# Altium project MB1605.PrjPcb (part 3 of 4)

## Sheet USB_HUB.SchDoc: USB_HUB
size A3; Date: Not used; ApprovedBy: Not used; CheckedBy: Not used; Author: Not used; CompanyName: STMicroelectronics; DrawnBy: Not used; Engineer: Not used; Organization: Not used; Address1: Not used; Address2: Not used; Address3: Not used; Address4: Not used; DocumentNumber: Not used; Revision: Not used; SheetNumber: 14; SheetTotal: 18
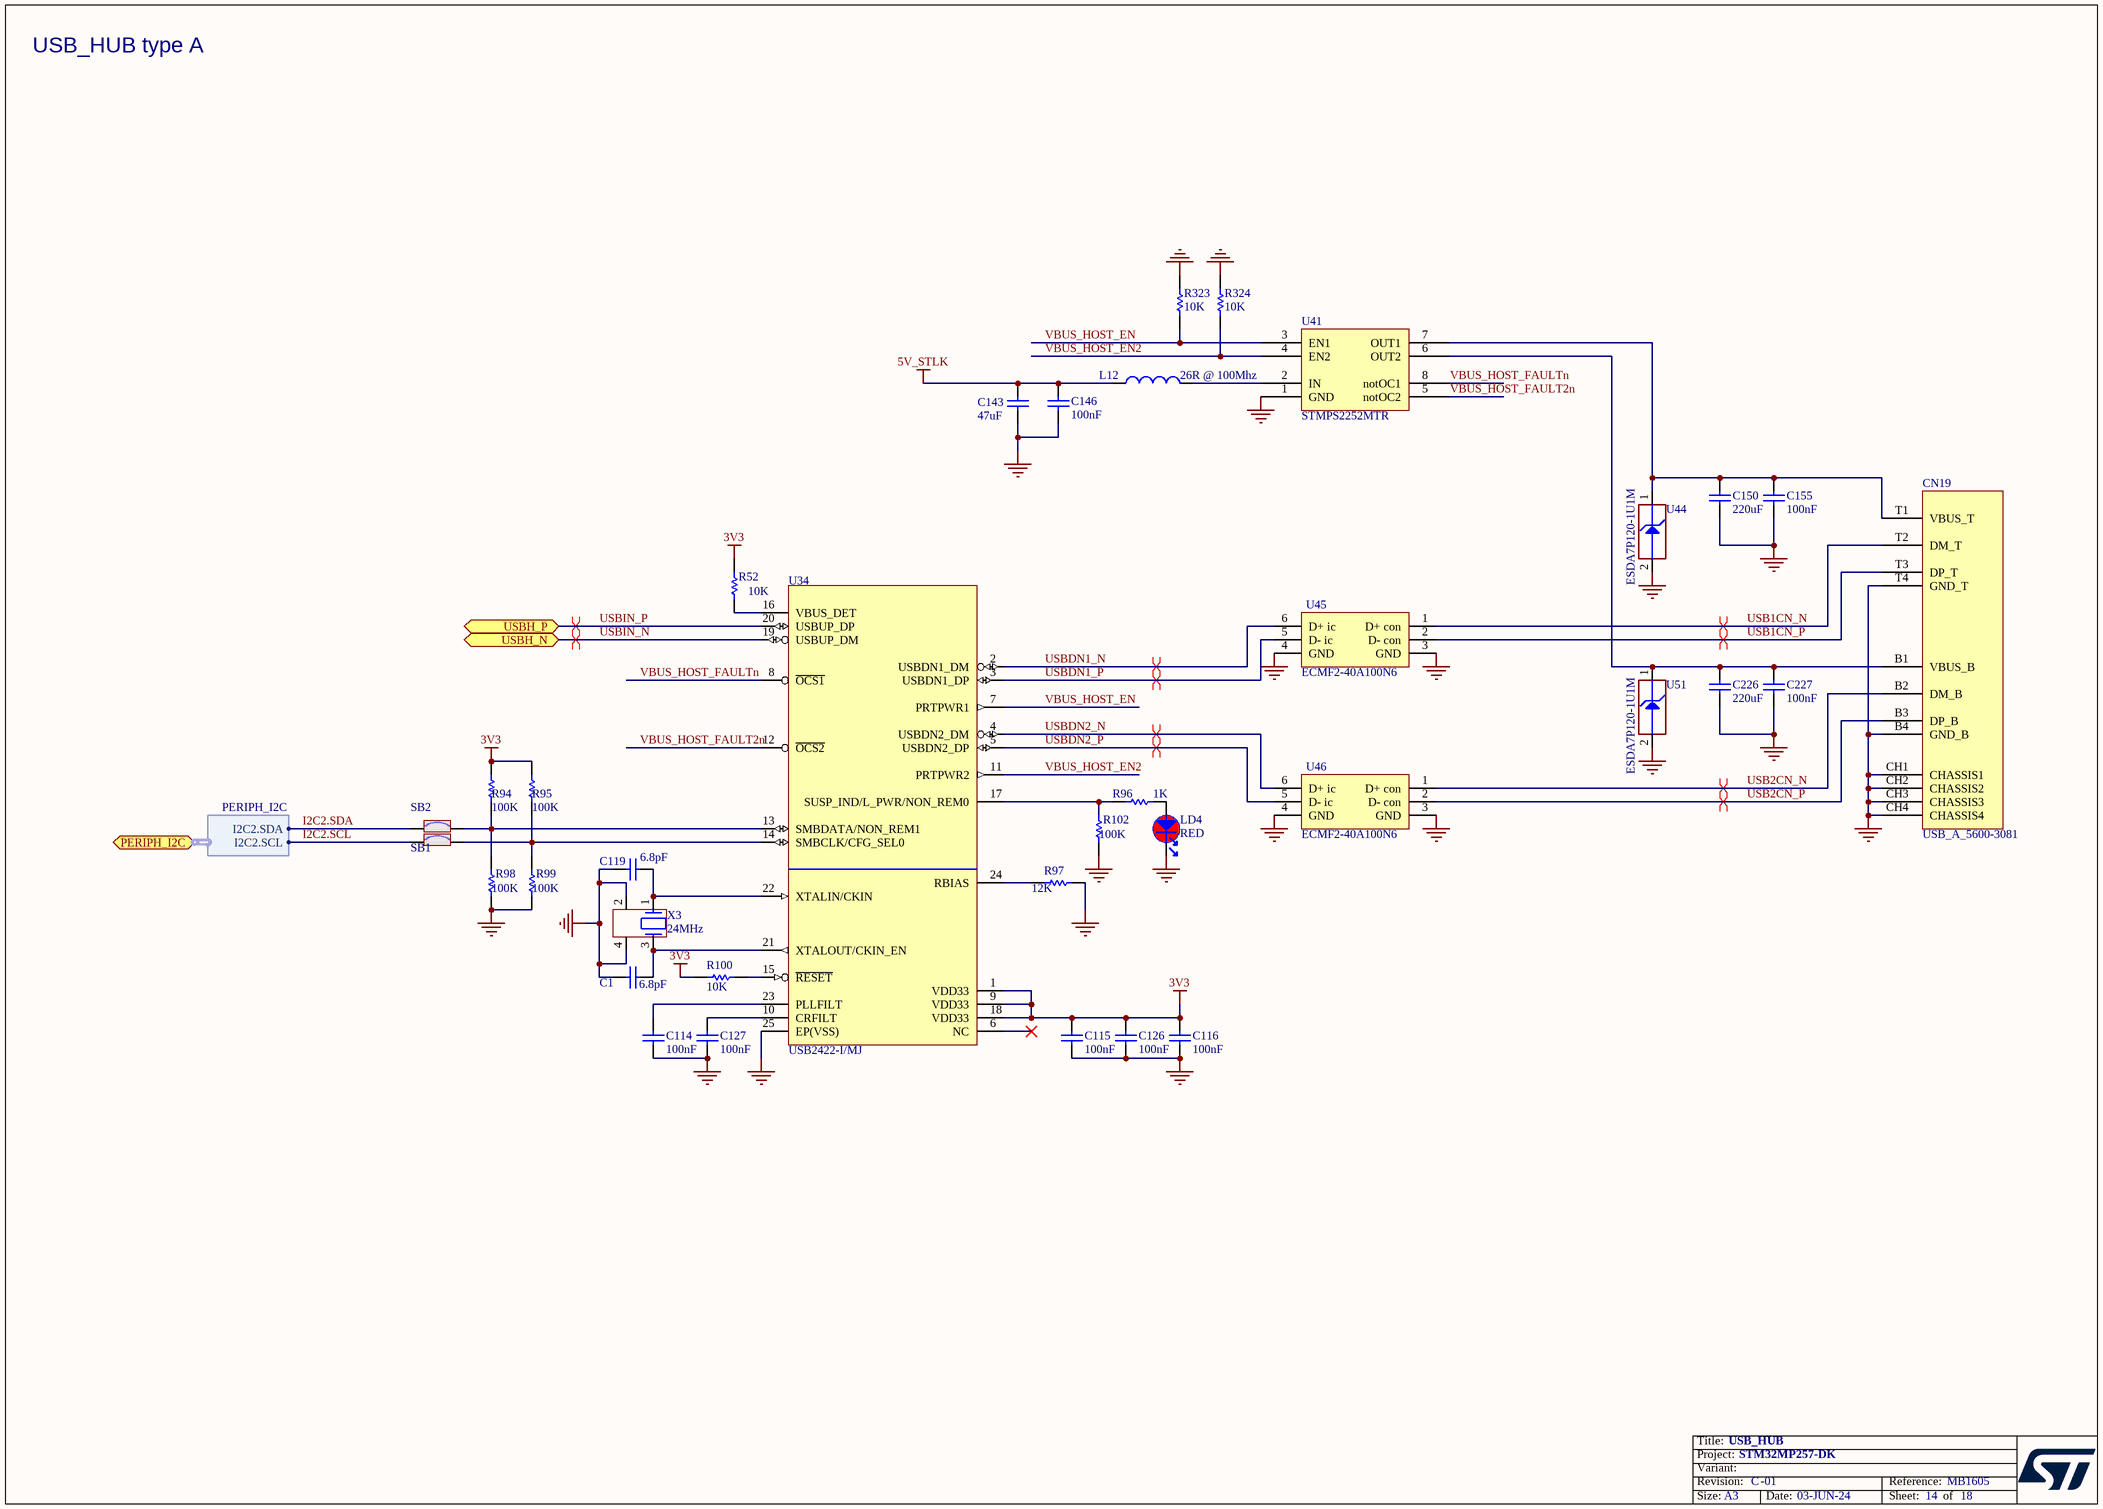
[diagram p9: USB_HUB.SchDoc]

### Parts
C1  value 6.8pF  [C0402]  (hidden comment: Capacitor)
C114  value 100nF  [C0402]  (hidden comment: Capacitor)
C115  value 100nF  [C0402]  (hidden comment: Capacitor)
C116  value 100nF  [C0402]  (hidden comment: Capacitor)
C119  value 6.8pF  [C0402]  (hidden comment: Capacitor)
C126  value 100nF  [C0402]  (hidden comment: Capacitor)
C127  value 100nF  [C0402]  (hidden comment: Capacitor)
C143  value 47uF  [C0805]  (hidden comment: Capacitor)
C146  value 100nF  [C0402]  (hidden comment: Capacitor)
C150  value 220uF  [C1206_H1P6]  (hidden comment: Capacitor)
C155  value 100nF  [C0402]  (hidden comment: Capacitor)
C226  value 220uF  [C1206_H1P6]  (hidden comment: Capacitor)
C227  value 100nF  [C0402]  (hidden comment: Capacitor)
CN19  value USB_A_5600-3081  [CON_DUAL-USB-TYPE-A_CONEXCON_5600-3081]  (hidden comment: USB_DUAL_TYPEA_5600-3081)
L12  value 26R @ 100Mhz  [FIL_0603_H0P65]  (hidden comment: BEAD)
LD4  value RED  [LED_0603_VISHAY_VLMS1300-GS08_RED_1A2K_H0P8]  (hidden comment: LED_red)
R52  value 10K  [R0402]  (hidden comment: Resistor)
R94  value 100K  [R0402]  (hidden comment: Resistor)
R95  value 100K  [R0402]  (hidden comment: Resistor)
R96  value 1K  [R0402]  (hidden comment: Resistor)
R97  value 12K  [R0402]  (hidden comment: Resistor)
R98  value 100K  [R0402]  (hidden comment: Resistor)
R99  value 100K  [R0402]  (hidden comment: Resistor)
R100  value 10K  [R0402]  (hidden comment: Resistor)
R102  value 100K  [R0402]  (hidden comment: Resistor)
R323  value 10K  [R0402]  (hidden comment: Resistor)
R324  value 10K  [R0402]  (hidden comment: Resistor)
SB1  SB_ON  [SOLDER-BRIDGE_R0603-0R]  (value not drawn)
SB2  SB_ON  [SOLDER-BRIDGE_R0603-0R]  (value not drawn)
U34  USB2422-I/MJ  [ICC_SQFN24-EPAD_4X4_P050]
U41  STMPS2252MTR  [ICC_SO8_5X4_P127]
U44  value ESDA7P120-1U1M  [ESD_QFN1610_2N_1K_2A]  (hidden comment: ESD-TRANSIL)
U45  ECMF2-40A100N6  [ESD_UQFN-6L_1P45X1P4_P040]
U46  ECMF2-40A100N6  [ESD_UQFN-6L_1P45X1P4_P040]
U51  value ESDA7P120-1U1M  [ESD_QFN1610_2N_1K_2A]  (hidden comment: ESD-TRANSIL)
X3  value 24MHz  [CRY_NX2016SA_4P]  (hidden comment: XTAL_4_PINS)

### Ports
PERIPH_I2C (bidir, harness PERIPH_I2C), USBH_N (bidir), USBH_P (bidir)

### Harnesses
PERIPH_I2C: I2C2.SDA, I2C2.SCL

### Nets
3V3: C115.2 C116.2 C126.2 R52.2 R94.2 R95.2 R100.1 U34.1(VDD33) U34.9(VDD33) U34.18(VDD33)
5V_STLK: C143.2 C146.2 L12.1
GND: C1.1 C114.1 C115.1 C116.1 C119.1 C126.1 C127.1 C143.1 C146.1 C150.1 C155.1 C226.1 C227.1 CN19.B4(GND_B) CN19.CH1(CHASSIS1) CN19.CH2(CHASSIS2) CN19.CH3(CHASSIS3) CN19.CH4(CHASSIS4) CN19.T4(GND_T) LD4.2 R97.1 R98.1 R99.1 R102.1 R323.1 R324.1 U34.25(EP(VSS)) U41.1(GND) U44.2(GND) U45.3(GND) U45.4(GND) U46.3(GND) U46.4(GND) U51.2(GND) X3.2 X3.4
I2C2.SCL: SB1.1 ; port PERIPH_I2C.I2C2.SCL
I2C2.SDA: SB2.1 ; port PERIPH_I2C.I2C2.SDA
USB1CN_N: CN19.T2(DM_T) U45.1(D+_con)
USB1CN_P: CN19.T3(DP_T) U45.2(D-_con)
USB2CN_N: CN19.B2(DM_B) U46.1(D+_con)
USB2CN_P: CN19.B3(DP_B) U46.2(D-_con)
USBDN1_N: U34.2(USBDN1_DM) U45.6(D+_ic)
USBDN1_P: U34.3(USBDN1_DP) U45.5(D-_ic)
USBDN2_N: U34.4(USBDN2_DM) U46.6(D+_ic)
USBDN2_P: U34.5(USBDN2_DP) U46.5(D-_ic)
USBIN_N: U34.19(USBUP_DM) ; port USBH_N  [project net USBH_N]
USBIN_P: U34.20(USBUP_DP) ; port USBH_P  [project net USBH_P]
VBUS_HOST_EN: R323.2 U34.7(PRTPWR1) U41.3(EN1)
VBUS_HOST_EN2: R324.2 U34.11(PRTPWR2) U41.4(EN2)
VBUS_HOST_FAULT2n: U34.12(~{OCS2}) U41.5(notOC2)
VBUS_HOST_FAULTn: U34.8(~{OCS1}) U41.8(notOC1)
NetC1_2: C1.2 U34.21(XTALOUT/CKIN_EN) X3.3
NetC114_2: C114.2 U34.23(PLLFILT)
NetC119_2: C119.2 U34.22(XTALIN/CKIN) X3.1
NetC127_2: C127.2 U34.10(CRFILT)
NetC150_2: C150.2 C155.2 CN19.T1(VBUS_T) U41.7(OUT1) U44.1(IO1)
NetC226_2: C226.2 C227.2 CN19.B1(VBUS_B) U41.6(OUT2) U51.1(IO1)
NetL12_2: L12.2 U41.2(IN)
NetLD4_1: LD4.1 R96.1
NetR52_1: R52.1 U34.16(VBUS_DET)
NetR94_1: R94.1 R98.2 SB2.2 U34.13(SMBDATA/NON_REM1)
NetR95_1: R95.1 R99.2 SB1.2 U34.14(SMBCLK/CFG_SEL0)
NetR96_2: R96.2 R102.2 U34.17(SUSP_IND/L_PWR/NON_REM0)
NetR97_2: R97.2 U34.24(RBIAS)
NetR100_2: R100.2 U34.15(~{RESET})

Not connected (* = marked no-connect by the designer): U34 6(NC)*

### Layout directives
differential pair: USB1CN_N, USB1CN_P, USB2CN_N, USB2CN_P, USBDN1_N, USBDN1_P, USBDN2_N, USBDN2_P, USBH_N, USBH_P

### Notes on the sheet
- USB_HUB type A

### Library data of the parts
C1 C119 = MCD-00674: Capacitor, MLCC, 6.8pF, 50V, NPO, +-0.25pF, 0402, T=0.5mm; Manufacturer_Part_Number: CC0402CRNPO9BN6R8; Manufacturer: YAGEO; Part_Preference: Recommended; Provided_By: SUBCO; Component_Country_Of_Origin: China; ID: 3068; ShowFields: YES
C114-C116 C126 C127 = MCD-00006: Capacitor, MLCC, 100nF, 16V, X7R, +/-10%, 0402, T=0.5mm; Manufacturer_Part_Number: CC0402KRX7R7BB104; Manufacturer: YAGEO; Alternate_Manufacturer: MURATA; Alternate_Manufacturer_Part_Number: GCM155R71C104KA55D; Part_Preference: Recommended; Partial_Alternate_Internal_Part_Number: MCD-03299; Order_Code_RS: 616-9701; Component_Country_Of_Origin: China; Alternate_EMS: M; ID: 2474; ShowFields: YES
C143 = MCD-00204: Capacitor, MLCC, 47uF, 10V, X5R, +/-20%, 0805, T=1.25mm; Part_Preference: Recommended; Manufacturer: MURATA; Manufacturer_Part_Number: GRM21BR61A476ME15K; Component_Country_Of_Origin: Japan; ShowFields: YES; ID: 2664
C146 C155 C227 = MCD-00006: Capacitor, MLCC, 100nF, 16V, X7R, +/-10%, 0402, T=0.5mm; Manufacturer_Part_Number: CC0402KRX7R7BB104; Manufacturer: YAGEO; Part_Preference: Recommended; Partial_Alternate_Internal_Part_Number: MCD-03299; Order_Code_RS: 616-9701; Component_Country_Of_Origin: China; Alternate_EMS: M; ID: 2474; ShowFields: YES
C150 C226 = MCD-00104: Capacitor, MLCC, 220uF, 6V3, X5R, +/-20%, 1206, T=1.6mm; Manufacturer_Part_Number: GRM31CR60J227ME11; Manufacturer: MURATA; Part_Preference: Recommended; Order_Code_RS: 170-6396; Component_Country_Of_Origin: Japan; ID: 2764; ShowFields: YES
CN19 = MCD-00109: USB_Dual-TypeA, Receptacle, 8pins, 2.5mm, RA, TH, T= 15.5mm; Manufacturer: CONEXCON; Part_Type: Connector; Part_Preference: Recommended; Component_Country_Of_Origin: Unknown; ID: 2756; ShowFields: YES
L12 = MCD-00305: Ferrite bead, 26R @ 100Mhz, +/-25%, 6000mA, 0R007, 0603, T=0.75mm; Manufacturer_Part_Number: BLM18KG260TN1; Manufacturer: MURATA; Part_Type: Inductor; Part_Preference: Recommended; Order_Code_RS: 747-4723; Component_Country_Of_Origin: Japan; ID: 2564; ShowFields: YES
LD4 = MCD-00587: LED Red, 0603 SMD, 2V Forward Voltage; Part_Type: Display; Manufacturer_Part_Number: VLMS1300-GS08; Manufacturer: VISHAY; Alternate_Manufacturer_Part_Number: LS Q976-NR-1; Alternate_Manufacturer: OSRAM OPTO SEMICONDUCTORS; Alternate_Internal_Part_Number: MCD-02401; Part_Preference: Recommended; Provided_By: SUBCO; Component_Country_Of_Origin: China; ID: 3154; ShowFields: YES
R52 R100 = MCD-00053: Resistor,10K,0402,1%,1/16W; Manufacturer_Part_Number: RC0402FR-0710KL; Manufacturer: YAGEO; BMS_Part_Number: 9131590; Part_Preference: Recommended; Provided_By: SUBCO; Initial_Board_Reference: MB1274; Component_Country_Of_Origin: China; ID: 2539; ShowFields: YES
R94 R95 R98 R99 R102 = MCD-00059: Resistor,100K,0402,1%,1/16W; Manufacturer_Part_Number: RC0402FR-07100KL; Manufacturer: YAGEO; Alternate_Manufacturer_Part_Number: RT0402FRE07100KL; Part_Preference: Recommended; Partial_Alternate_Internal_Part_Number: MCD-03301; Provided_By: SUBCO; Initial_Board_Reference: MB1274; Component_Country_Of_Origin: China; Alternate_EMS: M; ID: 2533; ShowFields: YES
R96 = MCD-00061: Resistor,1K,0402,1%,1/16W; Manufacturer_Part_Number: RC0402FR-071KL; Manufacturer: YAGEO; Part_Preference: Recommended; Provided_By: SUBCO; Initial_Board_Reference: MB1274; Component_Country_Of_Origin: China; ID: 2532; ShowFields: YES
R97 = MCD-00187: Resistor,12K,0402,1%,1/16W; Manufacturer_Part_Number: RC0402FR-0712KL; Manufacturer: YAGEO; BMS_Part_Number: 9131030; Part_Preference: Recommended; Provided_By: SUBCO; Component_Country_Of_Origin: China; ID: 2678; ShowFields: YES
R323 R324 = MCD-00053: Resistor, 10K, 0402, +/-1%, 1/16W; Manufacturer_Part_Number: RC0402FR-0710KL; Manufacturer: YAGEO; BMS_Part_Number: 9131590; Part_Preference: Recommended; Component_Country_Of_Origin: China; ID: 2539; ShowFields: YES
SB1 SB2 = MCD-00071: Solder Bridge ON; Part_Preference: Recommended; Part_Type: Misc; Manufacturer: YAGEO; Manufacturer_Part_Number: RC0603JR-070RL; ID: 2521; ShowFields: YES
U34 = MCD-02348: 2xPort USB 2.0 Hi-Speed Hub Controller; Part_Type: IC; Part_Preference: Recommended; Manufacturer: MICROCHIP; Order_Code_RS: 165-2143; Component_Country_Of_Origin: Unknown; ID: 4454; ShowFields: YES
U41 = MCD-00123: IC,Dual-Channel-Power-Switch,500mA,100mR,SO8; Manufacturer: STMICROELECTRONICS; BMS_Part_Number: 9159012; Part_Preference: Recommended; Manufacturer_HQ_COO: EU; Component_Country_Of_Origin: China; ID: 2746; ShowFields: YES
U44 U51 = MCD-01026: High power transient voltage suppressor; Part_Type: Diode; Manufacturer: STMICROELECTRONICS; BMS_Part_Number: 9179046; Part_Preference: Recommended; Manufacturer_HQ_COO: EU; Component_Country_Of_Origin: China; ID: 2997; ShowFields: YES
U45 U46 = MCD-03060: ESD protection & Common Filter High Speed serial Interfaces , 0.4 pitch; Part_Type: IC; Part_Preference: Recommended; Manufacturer: STMICROELECTRONICS; ShowFields: YES; ID: 5176; Component_Country_Of_Origin: China
X3 = MCD-01036: Crystal 24MHz, 6pF, +-20ppm, 80ohms max, SMD; Part_Type: Crystal_Osc; Manufacturer_Part_Number: NX2016SA-24MHZ-EXS00A-CS10820; Manufacturer: NDK; BMS_Part_Number: 9157045; Part_Preference: Recommended; Provided_By: SUBCO; Component_Country_Of_Origin: Unknown; ID: 2989; ShowFields: YES

## Sheet USB3.SchDoc: USB3
size A3; Date: Not used; ApprovedBy: Not used; CheckedBy: Not used; Author: Not used; CompanyName: STMicroelectronics; DrawnBy: Not used; Engineer: Not used; Organization: Not used; Address1: Not used; Address2: Not used; Address3: Not used; Address4: Not used; DocumentNumber: Not used; Revision: Not used; SheetNumber: 13; SheetTotal: 18
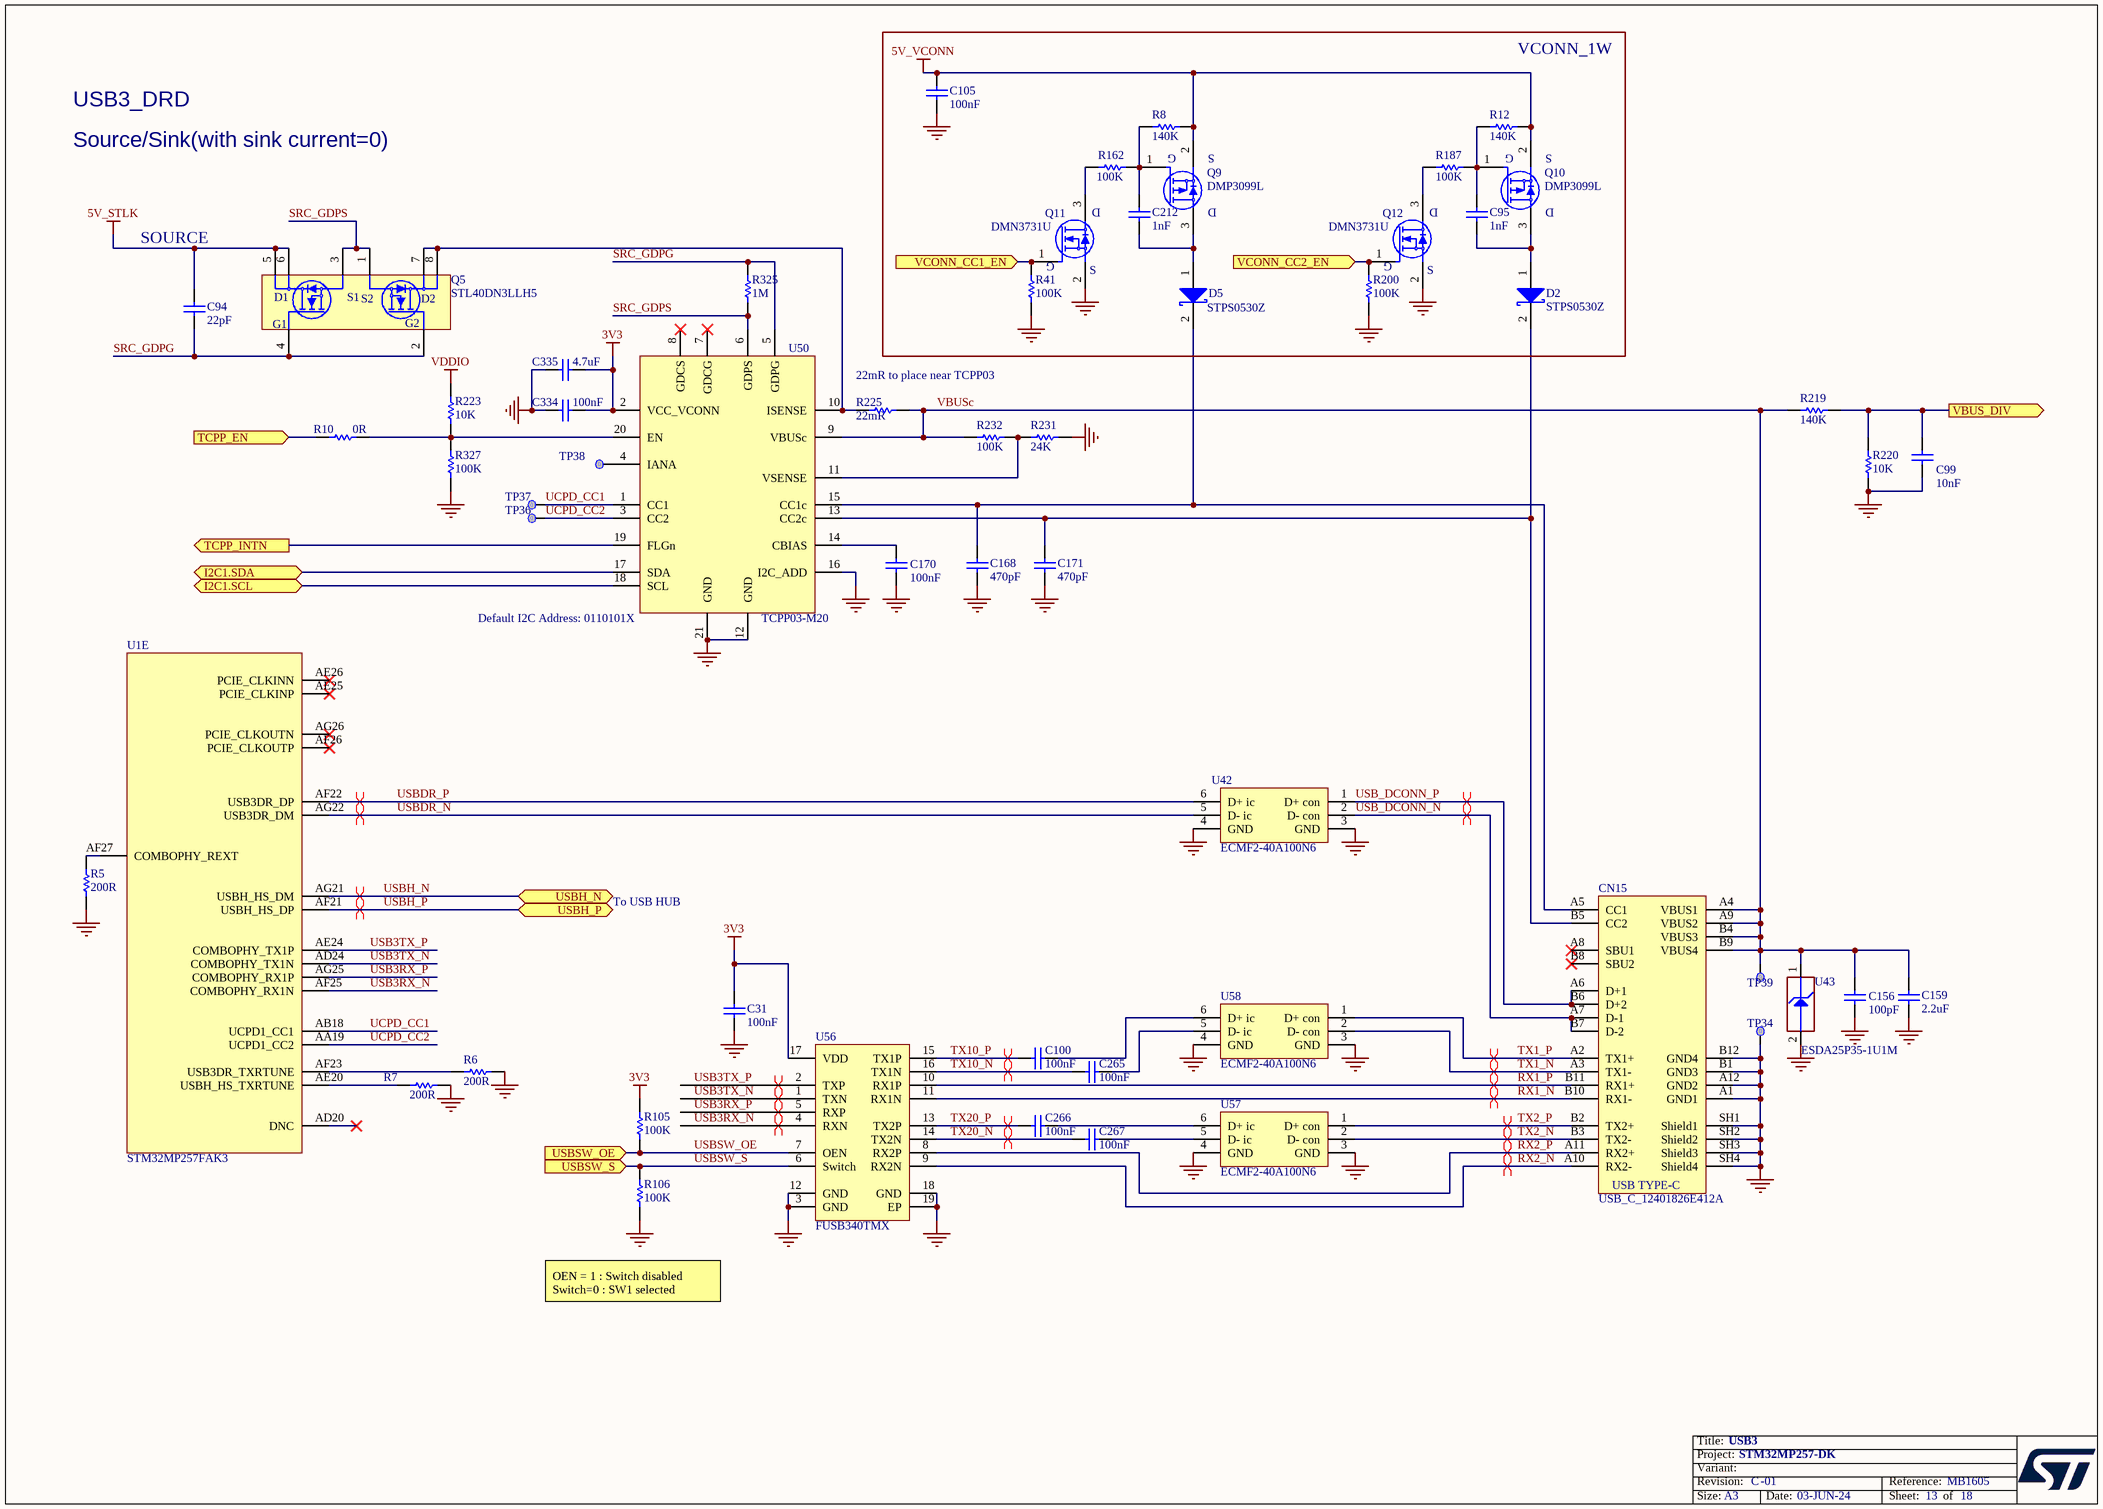
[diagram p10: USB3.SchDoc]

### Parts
C31  value 100nF  [C0402]  (hidden comment: Capacitor)
C94  value 22pF  [C0402]  (hidden comment: Capacitor)
C95  value 1nF  [C0402]  (hidden comment: Capacitor)
C99  value 10nF  [C0402]  (hidden comment: Capacitor)
C100  value 100nF  [C0201_H0P3]  (hidden comment: Capacitor)
C105  value 100nF  [C0402]  (hidden comment: Capacitor)
C156  value 100pF  [C0402]  (hidden comment: Capacitor)
C159  value 2.2uF  [C0805]  (hidden comment: Capacitor)
C168  value 470pF  [C0402]  (hidden comment: Capacitor)
C170  value 100nF  [C0603]  (hidden comment: Capacitor)
C171  value 470pF  [C0402]  (hidden comment: Capacitor)
C212  value 1nF  [C0402]  (hidden comment: Capacitor)
C265  value 100nF  [C0201_H0P3]  (hidden comment: Capacitor)
C266  value 100nF  [C0201_H0P3]  (hidden comment: Capacitor)
C267  value 100nF  [C0201_H0P3]  (hidden comment: Capacitor)
C334  value 100nF  [C0402]  (hidden comment: Capacitor)
C335  value 4.7uF  [C0402]  (hidden comment: Capacitor)
CN15  value USB_C_12401826E412A  [CON_USB-TYPEC_AMPHENOL_12401826E412A]  (hidden comment: USB_TYPE_C_Receptacle)
D2  value STPS0530Z  [DIO_SOD123_1A_2K_H1P45]  (hidden comment: SCHOTTKY_1A_2K)
D5  value STPS0530Z  [DIO_SOD123_1A_2K_H1P45]  (hidden comment: SCHOTTKY_1A_2K)
Q5  STL40DN3LLH5  [PowerFLAT_5x6]
Q9  value DMP3099L  [MOS_SOT23]  (hidden comment: MOSFET_P-CHANNEL)
Q10  value DMP3099L  [MOS_SOT23]  (hidden comment: MOSFET_P-CHANNEL)
Q11  value DMN3731U  [MOS_SOT23]  (hidden comment: MOSFET_N-CHANNEL)
Q12  value DMN3731U  [MOS_SOT23]  (hidden comment: MOSFET_N-CHANNEL)
R5  value 200R  [R0402]  (hidden comment: Resistor)
R6  value 200R  [R0402]  (hidden comment: Resistor)
R7  value 200R  [R0402]  (hidden comment: Resistor)
R8  value 140K  [R0402]  (hidden comment: Resistor)
R10  value 0R  [R0402]  (hidden comment: Resistor)
R12  value 140K  [R0402]  (hidden comment: Resistor)
R41  value 100K  [R0402]  (hidden comment: Resistor)
R105  value 100K  [R0402]  (hidden comment: Resistor)
R106  value 100K  [R0402]  (hidden comment: Resistor)
R162  value 100K  [R0402]  (hidden comment: Resistor)
R187  value 100K  [R0402]  (hidden comment: Resistor)
R200  value 100K  [R0402]  (hidden comment: Resistor)
R219  value 140K  [R0402]  (hidden comment: Resistor)
R220  value 10K  [R0402]  (hidden comment: Resistor)
R223  value 10K  [R0402]  (hidden comment: Resistor)
R225  value 22mR  [R0603]  (hidden comment: Resistor)
R231  value 24K  [R0402]  (hidden comment: Resistor)
R232  value 100K  [R0402]  (hidden comment: Resistor)
R325  value 1M  [R0402]  (hidden comment: Resistor)
R327  value 100K  [R0402]  (hidden comment: Resistor)
TP34  Test Point  [TP_SMD_1MM]  (value not drawn)  (no BOM)
TP36  Test Point  [TP_SMD_1MM]  (value not drawn)  (no BOM)
TP37  Test Point  [TP_SMD_1MM]  (value not drawn)  (no BOM)
TP38  Test Point  [TP_SMD_1MM]  (value not drawn)  (no BOM)
TP39  Test Point  [TP_SMD_1MM]  (value not drawn)  (no BOM)
U1  STM32MP257FAK3  [ICC_TFBGA424_14X14_P050_H1P20_CODE-B0A2]  (part E of 9)
U42  ECMF2-40A100N6  [ESD_UQFN-6L_1P45X1P4_P040]
U43  value ESDA25P35-1U1M  [ESD_QFN1610_2N_1K_2A]  (hidden comment: ESD-TRANSIL)
U50  TCPP03-M20  [ICC_QFN20-EPAD_4X4_P050]
U56  FUSB340TMX  [ICC_UQFN18-EPAD_2X2P80_P040]
U57  ECMF2-40A100N6  [ESD_UQFN-6L_1P45X1P4_P040]
U58  ECMF2-40A100N6  [ESD_UQFN-6L_1P45X1P4_P040]

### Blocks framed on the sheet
VCONN_1W: C95 C105 C212 D2 D5 Q9-Q12 R8 R12 R41 R162 R187 R200

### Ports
I2C1.SCL (bidir), I2C1.SDA (bidir), TCPP_EN (in), TCPP_INTN (out), USBH_N (bidir), USBH_P (bidir), USBSW_OE (in), USBSW_S (in), VBUS_DIV (out), VCONN_CC1_EN (in), VCONN_CC2_EN (in)

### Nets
3V3: C31.1 C334.1 C335.1 R105.2 U50.2(VCC_VCONN) U56.17(VDD)
5V_STLK: C94.2 Q5.5(D1) Q5.6(D1)
5V_VCONN: C105.1 Q9.2(S) Q10.2(S) R8.2 R12.2
GND: C31.2 C99.2 C105.2 C156.1 C159.1 C168.1 C170.1 C171.1 C334.2 C335.2 CN15.A1(GND1) CN15.A12(GND2) CN15.B1(GND3) CN15.B12(GND4) CN15.SH1(Shield1) CN15.SH2(Shield2) CN15.SH3(Shield3) CN15.SH4(Shield4) Q11.2(S) Q12.2(S) R5.1 R6.2 R7.2 R41.1 R106.1 R200.1 R220.1 R231.2 R327.1 TP34.1 U42.3(GND) U42.4(GND) U43.2(GND) U50.12(GND) U50.16(I2C_ADD) U50.21(GND) U56.3(GND) U56.12(GND) U56.18(GND) U56.19(EP) U57.3(GND) U57.4(GND) U58.3(GND) U58.4(GND)
VDDIO: R223.2
I2C1.SCL: U50.18(SCL) ; port I2C1.SCL
I2C1.SDA: U50.17(SDA) ; port I2C1.SDA
RX1_N: CN15.B10(RX1-) U56.11(RX1N)
RX1_P: CN15.B11(RX1+) U56.10(RX1P)
RX2_N: CN15.A10(RX2-) U56.9(RX2N)
RX2_P: CN15.A11(RX2+) U56.8(RX2P)
SRC_GDPG: C94.1 Q5.2(G2) Q5.4(G1) R325.2 U50.5(GDPG)
SRC_GDPS: Q5.1(S2) Q5.3(S1) R325.1 U50.6(GDPS)
TCPP_EN: R10.1 ; port TCPP_EN
TCPP_INTN: U50.19(FLGn) ; port TCPP_INTN
TX1_N: CN15.A3(TX1-) U58.2(D-_con)
TX1_P: CN15.A2(TX1+) U58.1(D+_con)
TX2_N: CN15.B3(TX2-) U57.2(D-_con)
TX2_P: CN15.B2(TX2+) U57.1(D+_con)
TX10_N: C265.1 U56.16(TX1N)
TX10_P: C100.1 U56.15(TX1P)
TX20_N: C267.1 U56.14(TX2N)
TX20_P: C266.1 U56.13(TX2P)
UCPD_CC1: TP37.1 U1.AB18(UCPD1_CC1) U50.1(CC1)
UCPD_CC2: TP36.1 U1.AA19(UCPD1_CC2) U50.3(CC2)
USB3RX_N: U1.AF25(COMBOPHY_RX1N) U56.4(RXN)
USB3RX_P: U1.AG25(COMBOPHY_RX1P) U56.5(RXP)
USB3TX_N: U1.AD24(COMBOPHY_TX1N) U56.1(TXN)
USB3TX_P: U1.AE24(COMBOPHY_TX1P) U56.2(TXP)
USB_DCONN_N: CN15.A7(D-1) CN15.B7(D-2) U42.2(D-_con)
USB_DCONN_P: CN15.A6(D+1) CN15.B6(D+2) U42.1(D+_con)
USBDR_N: U1.AG22(USB3DR_DM) U42.5(D-_ic)
USBDR_P: U1.AF22(USB3DR_DP) U42.6(D+_ic)
USBH_N: U1.AG21(USBH_HS_DM) ; port USBH_N
USBH_P: U1.AF21(USBH_HS_DP) ; port USBH_P
USBSW_OE: R105.1 U56.7(OEN) ; port USBSW_OE
USBSW_S: R106.2 U56.6(Switch) ; port USBSW_S
VBUS_DIV: C99.1 R219.1 R220.2 ; port VBUS_DIV
VBUSc: C156.2 C159.2 CN15.A4(VBUS1) CN15.A9(VBUS2) CN15.B4(VBUS3) CN15.B9(VBUS4) R219.2 R225.1 R232.1 TP39.1 U43.1(IO1) U50.9(VBUSc)
VCONN_CC1_EN: Q11.1(G) R41.2 ; port VCONN_CC1_EN
VCONN_CC2_EN: Q12.1(G) R200.2 ; port VCONN_CC2_EN
NetC95_1: C95.1 D2.1(A) Q10.3(D)
NetC95_2: C95.2 Q10.1(G) R12.1 R187.2
NetC100_2: C100.2 U58.6(D+_ic)
NetC168_2: C168.2 CN15.A5(CC1) D5.2(K) U50.15(CC1c)
NetC170_2: C170.2 U50.14(CBIAS)
NetC171_2: C171.2 CN15.B5(CC2) D2.2(K) U50.13(CC2c)
NetC212_1: C212.1 D5.1(A) Q9.3(D)
NetC212_2: C212.2 Q9.1(G) R8.1 R162.2
NetC265_2: C265.2 U58.5(D-_ic)
NetC266_2: C266.2 U57.6(D+_ic)
NetC267_2: C267.2 U57.5(D-_ic)
NetQ5_7: Q5.7(D2) Q5.8(D2) R225.2 U50.10(ISENSE)
NetQ11_3: Q11.3(D) R162.1
NetQ12_3: Q12.3(D) R187.1
NetR5_2: R5.2 U1.AF27(COMBOPHY_REXT)
NetR6_1: R6.1 U1.AF23(USB3DR_TXRTUNE)
NetR7_1: R7.1 U1.AE20(USBH_HS_TXRTUNE)
NetR10_2: R10.2 R223.1 R327.2 U50.20(EN)
NetR231_1: R231.1 R232.2 U50.11(VSENSE)
NetTP38_1: TP38.1 U50.4(IANA)

Not connected (* = marked no-connect by the designer): CN15 A8(SBU1)* B8(SBU2)*; U1 AD20(DNC)* AE25(PCIE_CLKINP)* AE26(PCIE_CLKINN)* AF26(PCIE_CLKOUTP)* AG26(PCIE_CLKOUTN)*; U50 7(GDCG)* 8(GDCS)*

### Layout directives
differential pair: RX1_N, RX1_P, RX2_N, RX2_P, TX1_N, TX1_P, TX2_N, TX2_P, TX10_N, TX10_P, TX20_N, TX20_P, USB3RX_N, USB3RX_P, USB3TX_N, USB3TX_P, USB_DCONN_N, USB_DCONN_P, USBDR_N, USBDR_P, USBH_N, USBH_P

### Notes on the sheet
- USB3_DRD
- Source/Sink(with sink current=0)
- SOURCE
- 22mR to place near TCPP03
- (near U50) Default I2C Address: 0110101X
- To USB HUB
- OEN = 1 : Switch disabled
  Switch=0 : SW1 selected

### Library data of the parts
C31 C105 C334 = MCD-00006: Capacitor, MLCC, 100nF, 16V, X7R, +/-10%, 0402, T=0.5mm; Part_Preference: Recommended; Manufacturer: YAGEO; Manufacturer_Part_Number: CC0402KRX7R7BB104; Partial_Alternate_Internal_Part_Number: MCD-03299; Order_Code_RS: 616-9701; Component_Country_Of_Origin: China; Alternate_EMS: M; ID: 2474; ShowFields: YES
C94 = MCD-01995: Capacitor, MLCC, 22pF, 50V, C0G, +/-5%, 0402, T=0.5mm; Part_Preference: Recommended; Manufacturer: TDK; Manufacturer_Part_Number: C1005NP01H220J050BA; Component_Country_Of_Origin: Unknown; ID: 4095; ShowFields: YES
C95 C212 = MCD-00198: Capacitor, MLCC, 1nF, 16V, X7R, +/-10%, 0402, T=0.5mm; Part_Preference: Recommended; Manufacturer: YAGEO; Manufacturer_Part_Number: CC0402KRX7R7BB102; Component_Country_Of_Origin: China; ShowFields: YES; ID: 2665
C99 = MCD-00011: Capacitor, MLCC, 10nF, 16V, X7R, 10%, 0402, T=0.5mm; Manufacturer_Part_Number: CC0402KRX7R7BB103; Manufacturer: YAGEO; Part_Preference: Recommended; Provided_By: SUBCO; Initial_Board_Reference: MB1274; Order_Code_RS: 669-8688
C100 C265-C267 = MCD-00697: Capacitor, MLCC, 100nF,10V, X5R, +/-10%, 0201, T=0.3mm; Part_Preference: Recommended; Manufacturer: TDK; Manufacturer_Part_Number: C0603X5R1A104K030BC; Component_Country_Of_Origin: Unknown; ID: 3046; ShowFields: YES
C156 = MCD-00205: Capacitor, MLCC, 100pF, 50V, NPO, +/-5%, 0402, T=0.5mm; Manufacturer_Part_Number: CC0402JRNPO9BN101; Manufacturer: YAGEO; Part_Preference: Recommended; Component_Country_Of_Origin: China; ID: 2658; ShowFields: YES
C159 = MCD-02372: Capacitor, MLCC, 2.2uF, 25V, X7R, +/-10%, 0805, T=1,25mm; Part_Preference: Recommended; Manufacturer: MURATA; Manufacturer_Part_Number: GRM21BR71E225KE11L; Component_Country_Of_Origin: Japan; ID: 4478; ShowFields: YES
C168 C171 = MCD-00724: Capacitor, MLCC, 470pF, 50V, NPO, +/-5%, 0402, T=0.5mm; Manufacturer_Part_Number: CC0402JRNPO9BN471; Manufacturer: YAGEO; Part_Preference: Recommended; Component_Country_Of_Origin: China; Order_Code_RS: 199-2186; ID: 3023; ShowFields: YES
C170 = MCD-01099: Capacitor, MLCC, 100nF, 50V, X7R, +/-10%, 0603, T=0.8mm; BMS_Part_Number: 9142278; Part_Preference: Recommended; Manufacturer: YAGEO; Manufacturer_Part_Number: CC0603KRX7R9BB104; Order_Code_RS: 669-8767; Component_Country_Of_Origin: China; ID: 3397; ShowFields: YES
C335 = MCD-01356: Capacitor, MLCC, 4.7uF, 6V3, X5R, +/-20%, 0402, T=0.5mm; Part_Preference: Recommended; Manufacturer: MURATA; Manufacturer_Part_Number: GRM155R60J475ME47; Order_Code_RS: 814-5230; Component_Country_Of_Origin: Japan; ID: 3456; ShowFields: YES
CN15 = MCD-03232: USB_TypeC, 24 pins, RA, SMD, T=2.96mm (USB Certified 3.1); Part_Type: Connector; Part_Preference: Recommended; Manufacturer: AMPHENOL ICC; Manufacturer_Part_Number: 12401826E412A; Component_Country_Of_Origin: China°; ShowFields: YES; ID: 5348
D2 D5 = MCD-03688: Diode, Schottky, 0V33, 0.5A , 30V, SOD123; Part_Preference: Recommended; Manufacturer: STMICROELECTRONICS; ShowFields: YES; ID: 5804
Q5 = MCD-02152: MOSFET, Dual N-channel 30 V, 0.016 Ω typ., 40 A, STripFET™ H5 Power MOSFET; Part_Preference: Recommended; Part_Type: Transistor; Manufacturer: STMICROELECTRONICS; Manufacturer_HQ_COO: EU; Component_Country_Of_Origin: China; ID: 4252; ShowFields: YES
Q9 Q10 = MCD-03690: Transistor, MOSFET, P-CH, 30V, 3.8A, SOT23; Part_Preference: Recommended; Manufacturer: DIODES INCORPORATED; ShowFields: YES; ID: 5806
Q11 Q12 = MCD-03691: Transistor, MOSFET, N-CH, 30V, 0.9A, SOT23; Part_Preference: Recommended; Manufacturer: DIODES INCORPORATED; Order_Code_RS: 206-0087; ShowFields: YES; ID: 5807
R5-R7 = MCD-00417: Resistor, 200R, 0402, +/-1%, 1/16W; Part_Preference: Recommended; Manufacturer: YAGEO; Manufacturer_Part_Number: RC0402FR-07200RL; Component_Country_Of_Origin: China; ID: 2860; ShowFields: YES
R8 R12 = MCD-02335: Resistor, 140K, 0402, +/-1%, 1/16W; Part_Preference: Recommended; Manufacturer: YAGEO; Manufacturer_Part_Number: RC0402FR-07140KL; Component_Country_Of_Origin: China; ShowFields: YES; ID: 4441
R10 = MCD-00052: Resistor,0R,0402,5%,1/16W; Manufacturer_Part_Number: RC0402JR-070RL; Manufacturer: YAGEO; Part_Preference: Recommended; Order_Code_RS: 618-5804; Component_Country_Of_Origin: China; ID: 2540; ShowFields: YES
R41 R162 R187 R200 = MCD-00059: Resistor, 100K, 0402, +/-1%, 1/16W; Part_Preference: Recommended; Manufacturer: YAGEO; Manufacturer_Part_Number: RC0402FR-07100KL; Partial_Alternate_Internal_Part_Number: MCD-03301; Component_Country_Of_Origin: China; Alternate_EMS: M; ShowFields: YES; ID: 2533
R105 R106 = MCD-00059: Resistor,100K,0402,1%,1/16W; Part_Preference: Recommended; Manufacturer: YAGEO; Manufacturer_Part_Number: RC0402FR-07100KL; Alternate_Manufacturer_Part_Number: RT0402FRE07100KL; Partial_Alternate_Internal_Part_Number: MCD-03301; Alternate_EMS: M; Component_Country_Of_Origin: China; ID: 2533; ShowFields: YES
R219 = MCD-02335: Resistor, 140K, 0402, +/-1%, 1/16W; Part_Preference: Recommended; Manufacturer: YAGEO; Manufacturer_Part_Number: RC0402FR-07140KL; Component_Country_Of_Origin: China; ID: 4441; ShowFields: YES
R220 R223 = MCD-00053: Resistor, 10K, 0402, +/-1%, 1/16W; BMS_Part_Number: 9131590; Part_Preference: Recommended; Manufacturer: YAGEO; Manufacturer_Part_Number: RC0402FR-0710KL; Component_Country_Of_Origin: China; ID: 2539; ShowFields: YES
R225 = MCD-02232: Resistor, 22mR, 0603, +/-1%, 1/3W; Part_Preference: Recommended; Manufacturer: PANASONIC; Manufacturer_Part_Number: ERJ-3BWFR022V; Order_Code_RS: 763-8671P; Component_Country_Of_Origin: Japan; ID: 4332; ShowFields: YES
R231 = MCD-00435: Resistor, 24K, 0402, +/-1%, 1/16W; Part_Preference: Recommended; Manufacturer: YAGEO; Manufacturer_Part_Number: RC0402FR-0724KL; Component_Country_Of_Origin: China; ShowFields: YES; ID: 2845
R232 R327 = MCD-02265: Resistor,100K,0402,0.5%,1/16W; Part_Preference: Recommended; Manufacturer: YAGEO; Manufacturer_Part_Number: RC0402DR-07100KL; Component_Country_Of_Origin: China; ShowFields: YES; ID: 4365
R325 = MCD-00182: Resistor, 1M, 0402, +/-1%, 1/16W; BMS_Part_Number: 9131778; Part_Preference: Recommended; Manufacturer: YAGEO; Manufacturer_Part_Number: RC0402FR-071ML; Order_Code_RS: 618-6194; Component_Country_Of_Origin: China; ShowFields: YES; ID: 2686
TP34 TP36-TP39 = MCD-00074: Test Point 1mm; Part_Type: Misc; Part_Preference: Recommended; ID: 2518; ShowFields: YES
U1 = MCD-03375: MPU , 2xCortex-A35@1.5GHz, Cortex-M33@400MHz, TFBGA 14x14, pitch 0.5, 648KB SRAM, With Crypto; Part_Type: IC; Part_Preference: Recommended; Manufacturer: STMICROELECTRONICS; Component_Country_Of_Origin: Unknown; ShowFields: YES; ID: 5491
U42 = MCD-03060: as U45 on sheet USB_HUB
U43 = MCD-01207: High power Transient voltage suppressor:25V/35A EOS and ESD transients protection.; BMS_Part_Number: 9179045; Part_Type: Diode; Part_Preference: Recommended; Manufacturer: STMICROELECTRONICS; Manufacturer_HQ_COO: EU; Component_Country_Of_Origin: China; ID: 3289; ShowFields: YES
U50 = MCD-02130: USB Type-C Port Protection for USB DRP Power Delivery, PPS compliant; Part_Preference: Recommended; Part_Type: IC; Manufacturer: STMICROELECTRONICS; Manufacturer_HQ_COO: EU; Component_Country_Of_Origin: Unknown; ID: 4230; ShowFields: YES
U56 = MCD-02300: Switch USB3.1 Superspeed 10 Gbps , Gen1 and Gen2; Part_Type: IC; Part_Preference: Recommended; Manufacturer: ON SEMICONDUCTOR; Component_Country_Of_Origin: Thailand; ID: 4400; ShowFields: YES
U57 U58 = MCD-03060: IC, ESD protection and Common Filter High Speed serial Interfaces, 10.7 GHz; Part_Preference: Recommended; Manufacturer: STMICROELECTRONICS; Component_Country_Of_Origin: China; ShowFields: YES; ID: 5176

## Sheet CAMERA.SchDoc: CAMERA
size A4; Date: Not used; ApprovedBy: Not used; CheckedBy: Not used; Author: Not used; CompanyName: STMicroelectronics; DrawnBy: Not used; Engineer: Not used; Organization: Not used; Address1: Not used; Address2: Not used; Address3: Not used; Address4: Not used; DocumentNumber: Not used; Revision: Not used; SheetNumber: 11; SheetTotal: 18
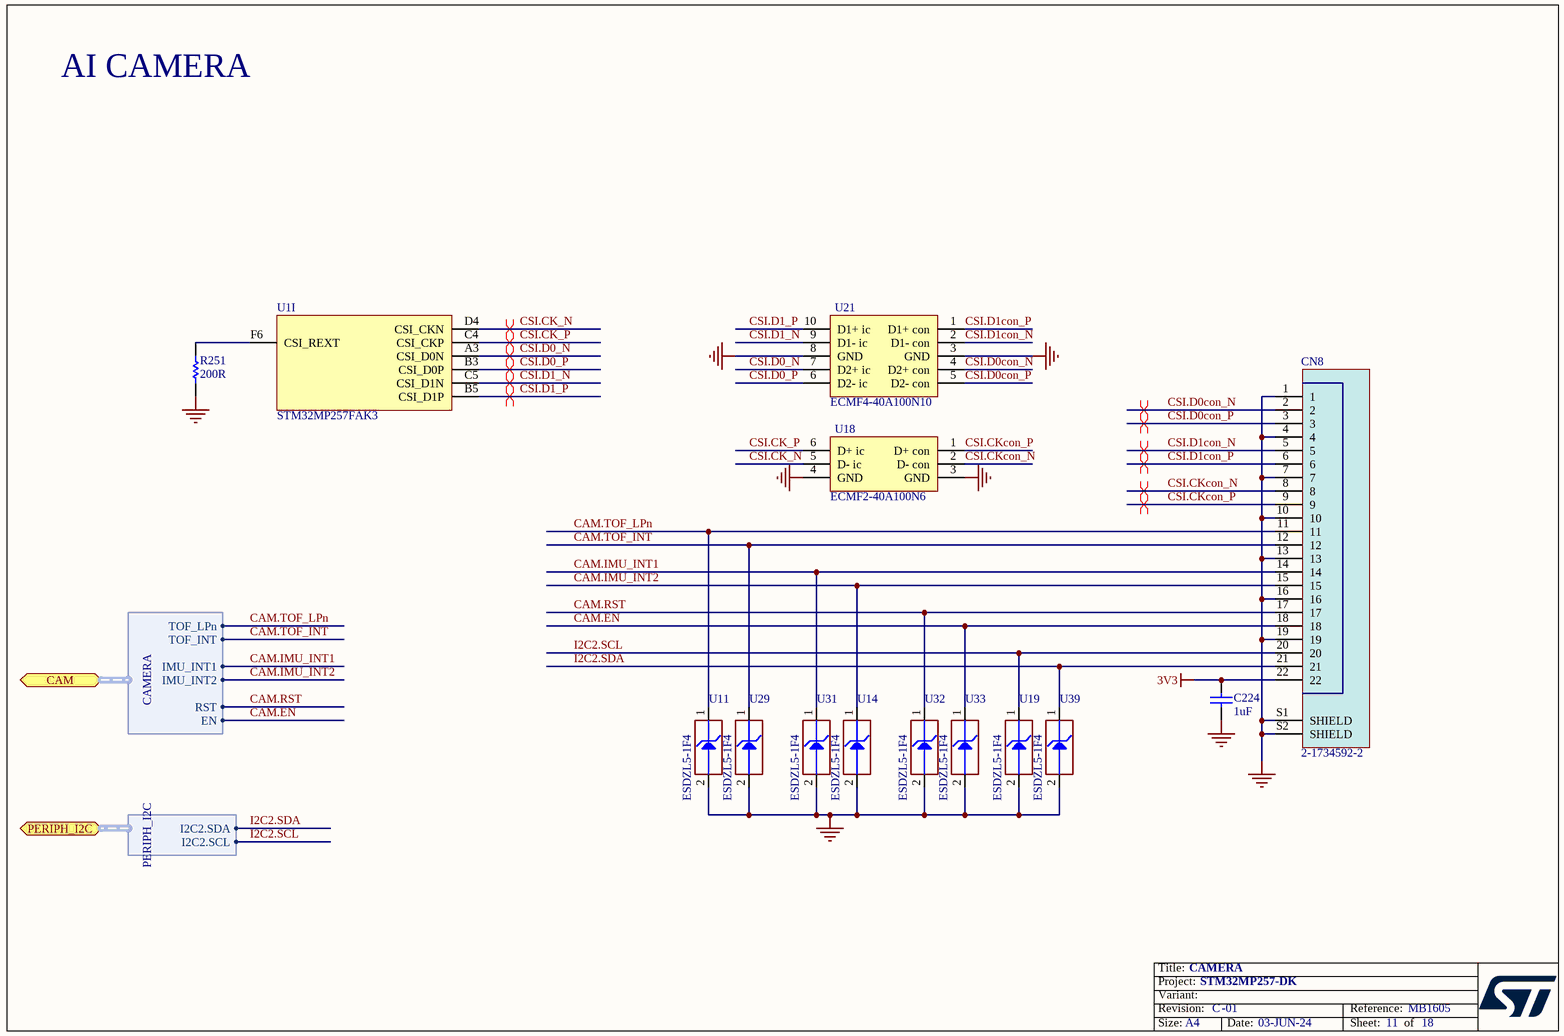
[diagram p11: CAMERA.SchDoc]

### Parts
C224  value 1uF  [C0402]  (hidden comment: Capacitor)
CN8  2-1734592-2  [CON_TE-CONNECTIVITY_2-1734592-2_INV]
R251  value 200R  [R0402]  (hidden comment: Resistor)
U1  STM32MP257FAK3  [ICC_TFBGA424_14X14_P050_H1P20_CODE-B0A2]  (part I of 9)
U11  value ESDZL5-1F4  [ESD_ST0201]  (hidden comment: ESD-TRANSIL)
U14  value ESDZL5-1F4  [ESD_ST0201]  (hidden comment: ESD-TRANSIL)
U18  ECMF2-40A100N6  [ESD_UQFN-6L_1P45X1P4_P040]
U19  value ESDZL5-1F4  [ESD_ST0201]  (hidden comment: ESD-TRANSIL)
U21  ECMF4-40A100N10  [ESD_UQFN-10L_2P25X1P4_P040]
U29  value ESDZL5-1F4  [ESD_ST0201]  (hidden comment: ESD-TRANSIL)
U31  value ESDZL5-1F4  [ESD_ST0201]  (hidden comment: ESD-TRANSIL)
U32  value ESDZL5-1F4  [ESD_ST0201]  (hidden comment: ESD-TRANSIL)
U33  value ESDZL5-1F4  [ESD_ST0201]  (hidden comment: ESD-TRANSIL)
U39  value ESDZL5-1F4  [ESD_ST0201]  (hidden comment: ESD-TRANSIL)

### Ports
CAM (bidir, harness CAMERA), PERIPH_I2C (bidir, harness PERIPH_I2C)

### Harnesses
PERIPH_I2C: I2C2.SDA, I2C2.SCL
CAMERA: TOF_LPn, TOF_INT, IMU_INT1, IMU_INT2, RST, EN

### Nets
3V3: C224.2 CN8.22
GND: C224.1 CN8.1 CN8.4 CN8.7 CN8.10 CN8.13 CN8.16 CN8.19 CN8.S1(SHIELD) CN8.S2(SHIELD) R251.2 U11.2(GND) U14.2(GND) U18.3(GND) U18.4(GND) U19.2(GND) U21.3(GND) U21.8(GND) U29.2(GND) U31.2(GND) U32.2(GND) U33.2(GND) U39.2(GND)
CAM.EN: CN8.18 U33.1(IO1) ; port CAM.EN
CAM.IMU_INT1: CN8.14 U31.1(IO1) ; port CAM.IMU_INT1
CAM.IMU_INT2: CN8.15 U14.1(IO1) ; port CAM.IMU_INT2
CAM.RST: CN8.17 U32.1(IO1) ; port CAM.RST
CAM.TOF_INT: CN8.12 U29.1(IO1) ; port CAM.TOF_INT
CAM.TOF_LPn: CN8.11 U11.1(IO1) ; port CAM.TOF_LPn
CSI.CK_N: U1.D4(CSI_CKN) U18.5(D-_ic)
CSI.CK_P: U1.C4(CSI_CKP) U18.6(D+_ic)
CSI.CKcon_N: CN8.8 U18.2(D-_con)
CSI.CKcon_P: CN8.9 U18.1(D+_con)
CSI.D0_N: U1.A3(CSI_D0N) U21.7(D2+_ic)
CSI.D0_P: U1.B3(CSI_D0P) U21.6(D2-_ic)
CSI.D0con_N: CN8.2 U21.4(D2+_con)
CSI.D0con_P: CN8.3 U21.5(D2-_con)
CSI.D1_N: U1.C5(CSI_D1N) U21.9(D1-_ic)
CSI.D1_P: U1.B5(CSI_D1P) U21.10(D1+_ic)
CSI.D1con_N: CN8.5 U21.2(D1-_con)
CSI.D1con_P: CN8.6 U21.1(D1+_con)
I2C2.SCL: CN8.20 U19.1(IO1) ; port PERIPH_I2C.I2C2.SCL
I2C2.SDA: CN8.21 U39.1(IO1) ; port PERIPH_I2C.I2C2.SDA
NetR251_1: R251.1 U1.F6(CSI_REXT)

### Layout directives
differential pair: CSI.CK_N, CSI.CK_P, CSI.CKcon_N, CSI.CKcon_P, CSI.D0_N, CSI.D0_P, CSI.D0con_N, CSI.D0con_P, CSI.D1_N, CSI.D1_P, CSI.D1con_N, CSI.D1con_P

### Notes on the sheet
- AI CAMERA

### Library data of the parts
C224 = MCD-00095: Capacitor, MLCC, 1uF, 25V, X5R, +/-10%, 0402, T=0,5mm; Manufacturer_Part_Number: GRM155R61E105KA12; Manufacturer: MURATA; Part_Preference: Recommended; Alternate_Manufacturer_Part_Number: GRM155R60J105KE19; Order_Code_RS: 846-7287; Component_Country_Of_Origin: Japan; ID: 2772; ShowFields: YES
CN8 = MCD-03600: Socket_FFC/FPC, 22pins, 0.5mm, RA, SMD, T=2mm; Part_Type: Connector; Part_Preference: Recommended; Manufacturer: TE CONNECTIVITY; Component_Country_Of_Origin: China°; ShowFields: YES; ID: 5716
R251 = MCD-00417: Resistor, 200R, 0402, +/-1%, 1/16W; Manufacturer_Part_Number: RC0402FR-07200RL; Manufacturer: YAGEO; Part_Preference: Recommended; Component_Country_Of_Origin: China; ID: 2860; ShowFields: YES
U1 = MCD-03375: as U1 on sheet USB3
U11 U14 U19 U29 U31-U33 U39 = MCD-03501: ESD protection , 0201; Part_Type: IC; Part_Preference: Recommended; Manufacturer: STMICROELECTRONICS; ShowFields: YES; ID: 5617; Order_Code_RS: 163-7318
U18 = MCD-03060: as U45 on sheet USB_HUB
U21 = MCD-03059: ESD protection & Common Filter High Speed serial Interfaces , 0.4 pitch; Part_Type: IC; Part_Preference: Recommended; Manufacturer: STMICROELECTRONICS; ShowFields: YES; ID: 5175; Component_Country_Of_Origin: China

## Sheet AUDIO.SchDoc: AUDIO
size A4; Date: Not used; ApprovedBy: Not used; CheckedBy: Not used; Author: Not used; CompanyName: STMicroelectronics; DrawnBy: Not used; Engineer: Not used; Organization: Not used; Address1: Not used; Address2: Not used; Address3: Not used; Address4: Not used; DocumentNumber: Not used; Revision: Not used; SheetNumber: 15; SheetTotal: 18
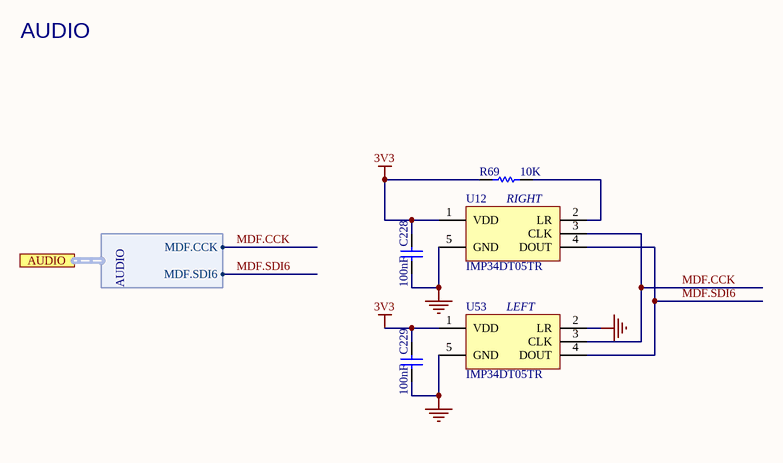
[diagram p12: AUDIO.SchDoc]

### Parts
C228  value 100nF  [C0402]
C229  value 100nF  [C0402]
R69  value 10K  [R0402]  (hidden comment: Resistor)
U12  IMP34DT05TR  [MIC_HCLGA_3X4X1_4LD]
U53  IMP34DT05TR  [MIC_HCLGA_3X4X1_4LD]

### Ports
AUDIO (harness AUDIO)

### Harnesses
AUDIO: MDF.CCK, MDF.SDI6

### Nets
3V3: C228.1 C229.1 R69.1 U12.1(VDD) U53.1(VDD)
GND: C228.2 C229.2 U12.5(GND) U53.2(LR) U53.5(GND)
MDF.CCK: U12.3(CLK) U53.3(CLK) ; port AUDIO.MDF.CCK
MDF.SDI6: U12.4(DOUT) U53.4(DOUT) ; port AUDIO.MDF.SDI6
NetR69_2: R69.2 U12.2(LR)

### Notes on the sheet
- AUDIO
- RIGHT
- (near U53) LEFT

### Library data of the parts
C228 C229 = MCD-00006: Capacitor,100nF,16V,X7R,10%,0402; Manufacturer_Part_Number: CC0402KRX7R7BB104; Manufacturer: YAGEO; Alternate_Manufacturer: MURATA; Alternate_Manufacturer_Part_Number: GCM155R71C104KA55D; Part_Preference: Recommended; Partial_Alternate_Internal_Part_Number: MCD-03299; Provided_By: SUBCO; Initial_Board_Reference: mb1274; Order_Code_RS: 616-9701; Alternate_EMS: M; Component_Country_Of_Origin: China; ID: 2474; ShowFields: YES
R69 = MCD-00053: Resistor,10K,0402,1%,1/16W; BMS_Part_Number: 9131590; Part_Preference: Recommended; Manufacturer: YAGEO; Manufacturer_Part_Number: RC0402FR-0710KL; Component_Country_Of_Origin: China; ID: 2539; ShowFields: YES
U12 U53 = MCD-01715: MEMS audio sensor omnidirectional digital microphone for industrial applications; BMS_Part_Number: 9177995; Part_Preference: Recommended; Part_Type: IC; Manufacturer: STMICROELECTRONICS; Manufacturer_HQ_COO: EU; Component_Country_Of_Origin: Philippines; ID: 3815; ShowFields: YES

## Sheet Expansion_Connector.SchDoc: EXPANSION_Connector
size A4; CompanyName: STMicroelectronics; Organization: Microcontrollers Division; Address1: 12, Rue Jules HOROWITZ; Address2: 38019 Grenoble; Address3: FRANCE; DocumentNumber: MB1272; Revision: A-01; SheetNumber: 16; SheetTotal: 18; Project: STM32MP15-DISCO PI
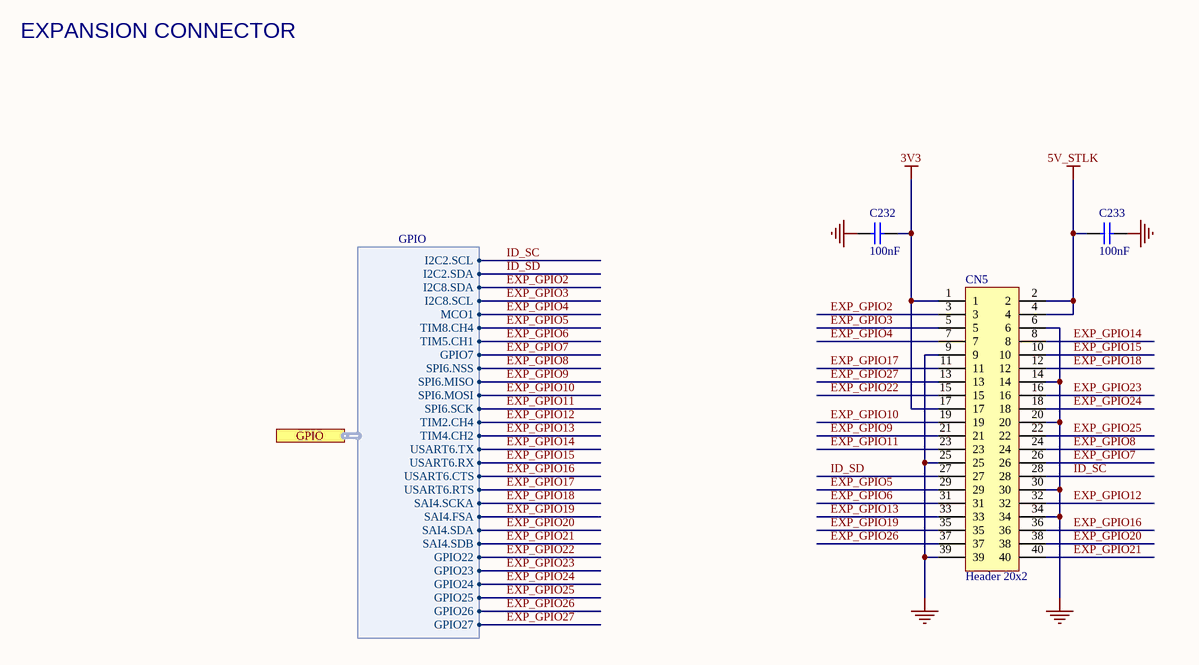
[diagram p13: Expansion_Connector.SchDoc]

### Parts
C232  value 100nF  [C0402]  (hidden comment: Capacitor)
C233  value 100nF  [C0402]  (hidden comment: Capacitor)
CN5  Header 20x2  [CON_SAMTEC_TSW-120-07-G-D]

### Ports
GPIO (harness GPIO)

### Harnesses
GPIO: I2C2.SCL, I2C2.SDA, I2C8.SDA, MCO1, TIM8.CH4, TIM5.CH1, GPIO7, SPI6.NSS, SPI6.MISO, SPI6.MOSI, SPI6.SCK, TIM2.CH4, TIM4.CH2, USART6.TX, USART6.RX, USART6.CTS, USART6.RTS, I2C8.SCL, SAI4.SCKA, SAI4.FSA, SAI4.SDA, SAI4.SDB, GPIO22, GPIO23, GPIO24, GPIO25, GPIO26, GPIO27

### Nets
3V3: C232.1 CN5.1 CN5.17
5V_STLK: C233.2 CN5.2 CN5.4
GND: C232.2 C233.1 CN5.6 CN5.9 CN5.14 CN5.20 CN5.25 CN5.30 CN5.34 CN5.39
EXP_GPIO2: CN5.3 ; port GPIO.I2C8.SDA
EXP_GPIO3: CN5.5 ; port GPIO.I2C8.SCL
EXP_GPIO4: CN5.7 ; port GPIO.MCO1
EXP_GPIO5: CN5.29 ; port GPIO.TIM8.CH4
EXP_GPIO6: CN5.31 ; port GPIO.TIM5.CH1
EXP_GPIO7: CN5.26 ; port GPIO.GPIO7
EXP_GPIO8: CN5.24 ; port GPIO.SPI6.NSS
EXP_GPIO9: CN5.21 ; port GPIO.SPI6.MISO
EXP_GPIO10: CN5.19 ; port GPIO.SPI6.MOSI
EXP_GPIO11: CN5.23 ; port GPIO.SPI6.SCK
EXP_GPIO12: CN5.32 ; port GPIO.TIM2.CH4
EXP_GPIO13: CN5.33 ; port GPIO.TIM4.CH2
EXP_GPIO14: CN5.8 ; port GPIO.USART6.TX
EXP_GPIO15: CN5.10 ; port GPIO.USART6.RX
EXP_GPIO16: CN5.36 ; port GPIO.USART6.CTS
EXP_GPIO17: CN5.11 ; port GPIO.USART6.RTS
EXP_GPIO18: CN5.12 ; port GPIO.SAI4.SCKA
EXP_GPIO19: CN5.35 ; port GPIO.SAI4.FSA
EXP_GPIO20: CN5.38 ; port GPIO.SAI4.SDA
EXP_GPIO21: CN5.40 ; port GPIO.SAI4.SDB
EXP_GPIO22: CN5.15 ; port GPIO.GPIO22
EXP_GPIO23: CN5.16 ; port GPIO.GPIO23
EXP_GPIO24: CN5.18 ; port GPIO.GPIO24
EXP_GPIO25: CN5.22 ; port GPIO.GPIO25
EXP_GPIO26: CN5.37 ; port GPIO.GPIO26
EXP_GPIO27: CN5.13 ; port GPIO.GPIO27
ID_SC: CN5.28 ; port GPIO.I2C2.SCL  [project net I2C2.SCL]
ID_SD: CN5.27 ; port GPIO.I2C2.SDA  [project net I2C2.SDA]

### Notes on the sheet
- EXPANSION CONNECTOR

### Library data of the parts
C232 C233 = MCD-00006: Capacitor, MLCC, 100nF, 16V, X7R, +/-10%, 0402, T=0.5mm; Part_Preference: Recommended; Manufacturer: YAGEO; Manufacturer_Part_Number: CC0402KRX7R7BB104; Partial_Alternate_Internal_Part_Number: MCD-03299; Order_Code_RS: 616-9701; Component_Country_Of_Origin: China; ShowFields: YES; ID: 2474; Alternate_EMS: M
CN5 = MCD-00302: Header, 20x2, 2.54mm, VR, TH, T=5.84mm/2.54mm; Manufacturer_Part_Number: TSW-120-07-G-D; Manufacturer: SAMTEC; Part_Type: Connector; Part_Preference: Recommended; Order_Code_RS: 180-2456; Component_Country_Of_Origin: China, Costa Rica, Malaysia, United States, Vietnam; ShowFields: YES; ID: 2567

## Sheet LPDDR4.SchDoc: LPDDR4
size A3; Date: Not used; ApprovedBy: Not used; CheckedBy: Not used; Author: Not used; CompanyName: STMicroelectronics; DrawnBy: Not used; Engineer: Not used; Organization: Not used; Address1: Not used; Address2: Not used; Address3: Not used; Address4: Not used; DocumentNumber: Not used; Revision: Not used; SheetNumber: 6; SheetTotal: 18
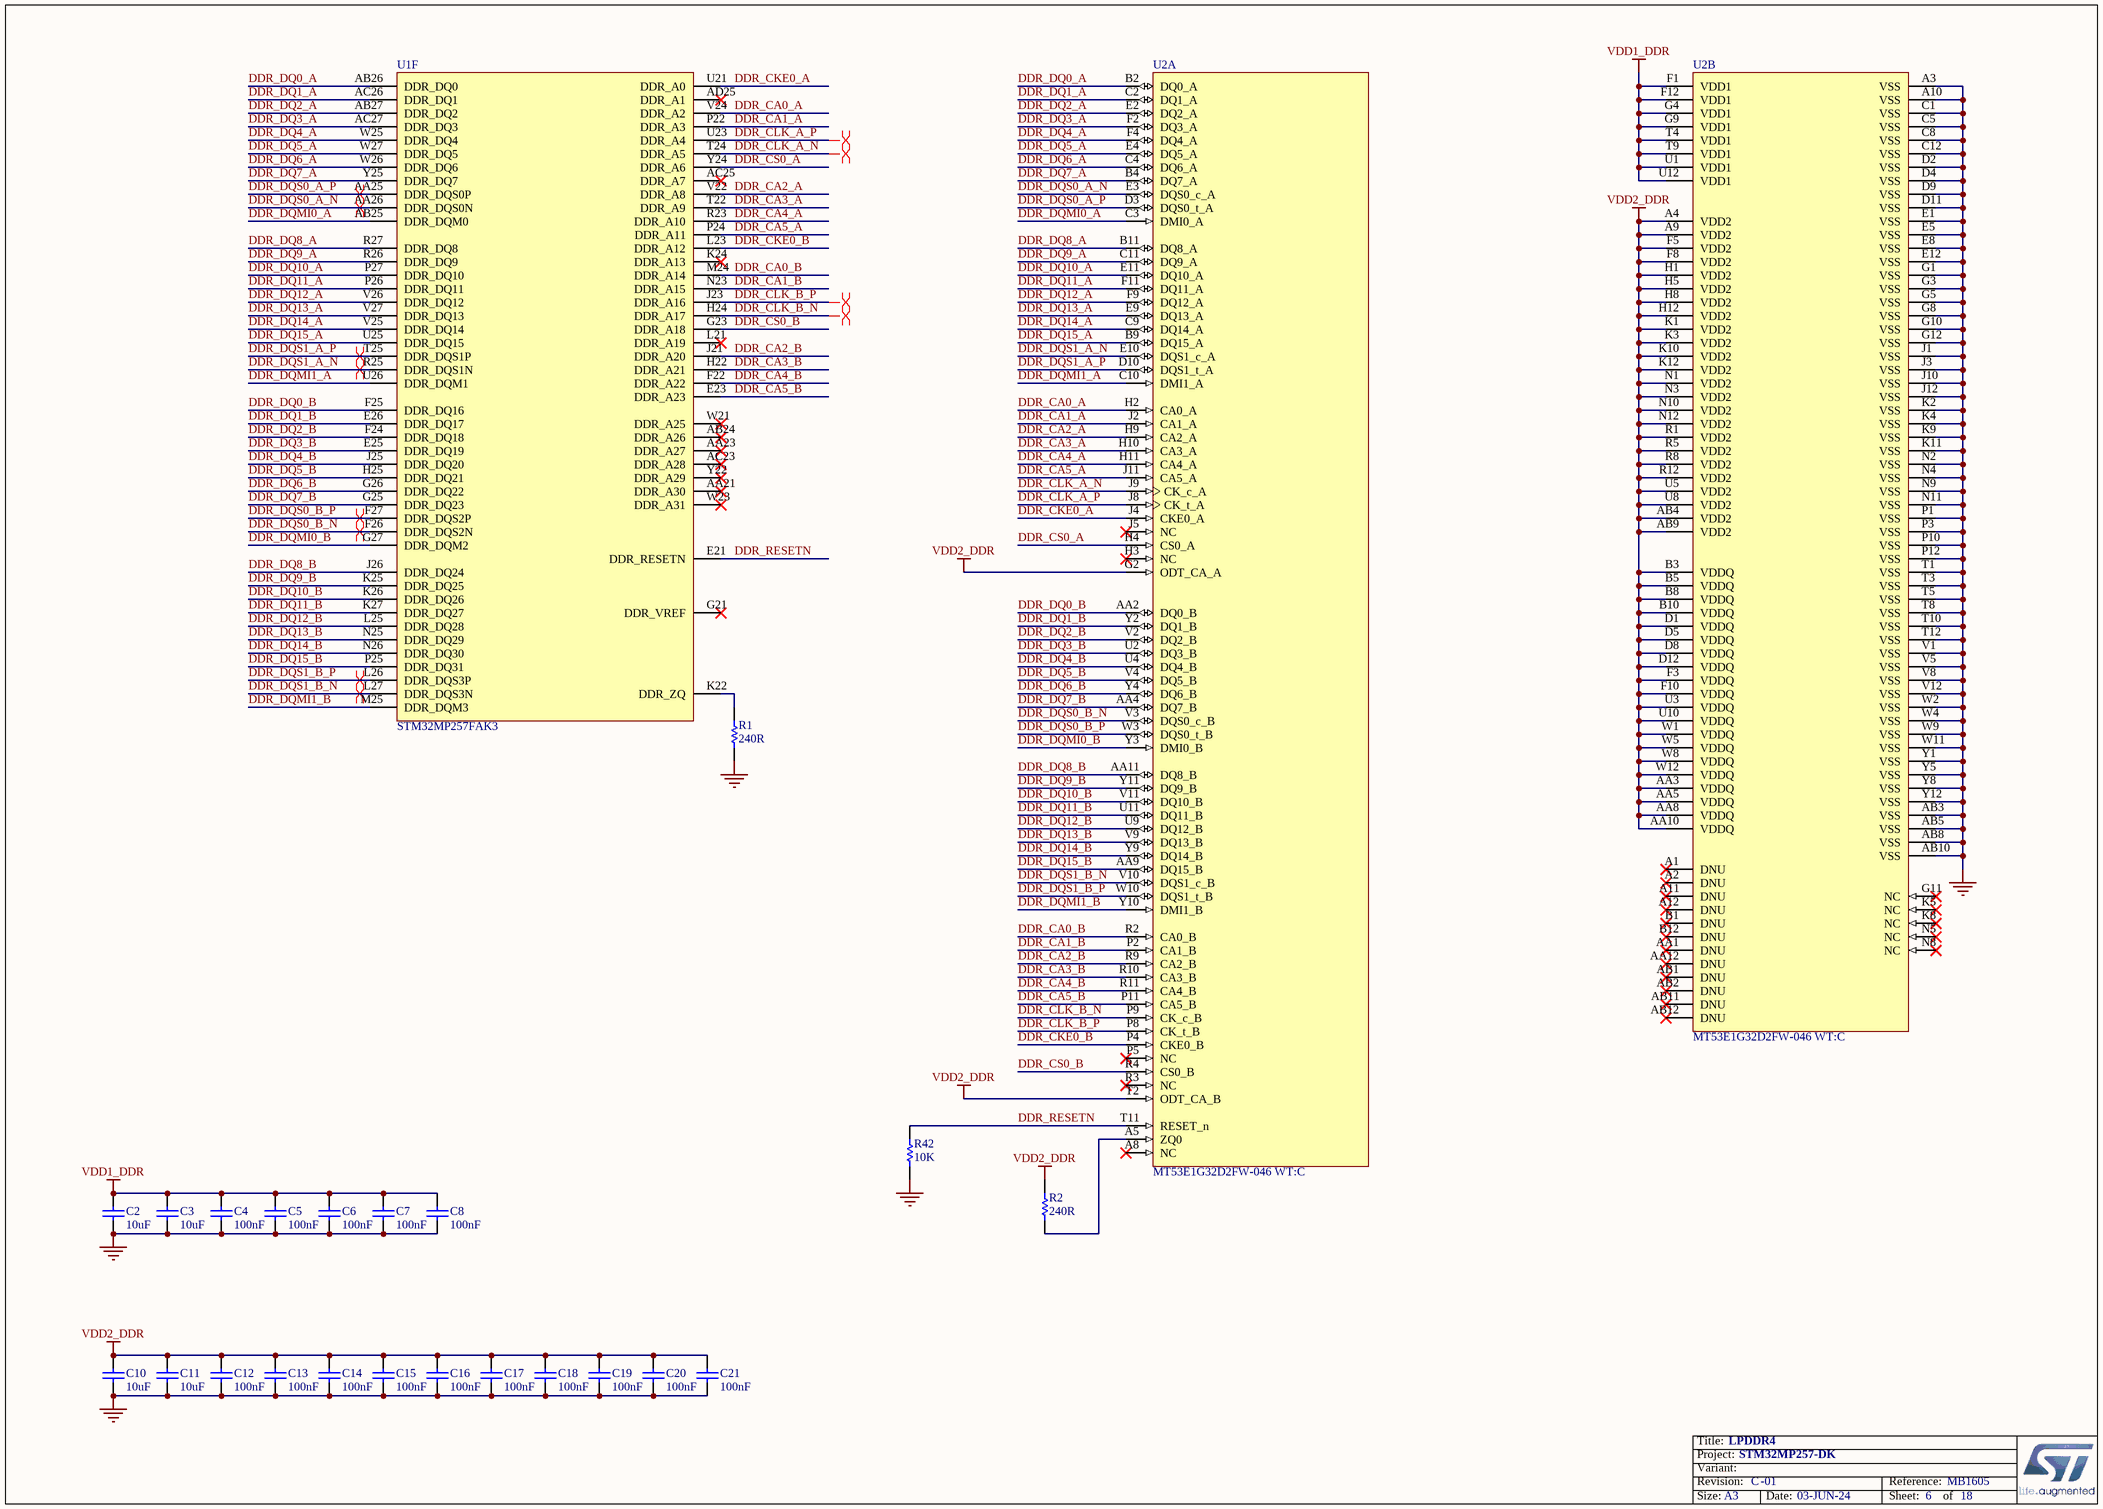
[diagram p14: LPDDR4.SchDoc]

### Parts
C2  value 10uF  [C0603]  (hidden comment: Capacitor)
C3  value 10uF  [C0603]  (hidden comment: Capacitor)
C4  100nF  [C0402]
C5  100nF  [C0402]
C6  100nF  [C0402]
C7  100nF  [C0402]
C8  100nF  [C0402]
C10  value 10uF  [C0603]  (hidden comment: Capacitor)
C11  value 10uF  [C0603]  (hidden comment: Capacitor)
C12  100nF  [C0402]
C13  100nF  [C0402]
C14  100nF  [C0402]
C15  100nF  [C0402]
C16  100nF  [C0402]
C17  100nF  [C0402]
C18  100nF  [C0402]
C19  100nF  [C0402]
C20  100nF  [C0402]
C21  100nF  [C0402]
R1  value 240R  [R0201_H0P23]  (hidden comment: Resistor)
R2  value 240R  [R0201_H0P23]  (hidden comment: Resistor)
R42  value 10K  [R0402]  (hidden comment: Resistor)
U1  STM32MP257FAK3  [ICC_TFBGA424_14X14_P050_H1P20_CODE-B0A2]  (part F of 9)
U2  MT53E1G32D2FW-046 WT:C  [ICC_TFBGA200_10X14P5_P080_H1P05_PS0P3]  (parts A,B of 2)

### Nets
GND: C2.1 C3.1 C4.2 C5.2 C6.2 C7.2 C8.2 C10.1 C11.1 C12.2 C13.2 C14.2 C15.2 C16.2 C17.2 C18.2 C19.2 C20.2 C21.2 R1.1 R42.1 U2.A3(VSS) U2.A10(VSS) U2.AB3(VSS) U2.AB5(VSS) U2.AB8(VSS) U2.AB10(VSS) U2.C1(VSS) U2.C5(VSS) U2.C8(VSS) U2.C12(VSS) U2.D2(VSS) U2.D4(VSS) U2.D9(VSS) U2.D11(VSS) U2.E1(VSS) U2.E5(VSS) U2.E8(VSS) U2.E12(VSS) U2.G1(VSS) U2.G3(VSS) U2.G5(VSS) U2.G8(VSS) U2.G10(VSS) U2.G12(VSS) U2.J1(VSS) U2.J3(VSS) U2.J10(VSS) U2.J12(VSS) U2.K2(VSS) U2.K4(VSS) U2.K9(VSS) U2.K11(VSS) U2.N2(VSS) U2.N4(VSS) U2.N9(VSS) U2.N11(VSS) U2.P1(VSS) U2.P3(VSS) U2.P10(VSS) U2.P12(VSS) U2.T1(VSS) U2.T3(VSS) U2.T5(VSS) U2.T8(VSS) U2.T10(VSS) U2.T12(VSS) U2.V1(VSS) U2.V5(VSS) U2.V8(VSS) U2.V12(VSS) U2.W2(VSS) U2.W4(VSS) U2.W9(VSS) U2.W11(VSS) U2.Y1(VSS) U2.Y5(VSS) U2.Y8(VSS) U2.Y12(VSS)
VDD1_DDR: C2.2 C3.2 C4.1 C5.1 C6.1 C7.1 C8.1 U2.F1(VDD1) U2.F12(VDD1) U2.G4(VDD1) U2.G9(VDD1) U2.T4(VDD1) U2.T9(VDD1) U2.U1(VDD1) U2.U12(VDD1)
VDD2_DDR: C10.2 C11.2 C12.1 C13.1 C14.1 C15.1 C16.1 C17.1 C18.1 C19.1 C20.1 C21.1 R2.2 U2.A4(VDD2) U2.A9(VDD2) U2.AA3(VDDQ) U2.AA5(VDDQ) U2.AA8(VDDQ) U2.AA10(VDDQ) U2.AB4(VDD2) U2.AB9(VDD2) U2.B3(VDDQ) U2.B5(VDDQ) U2.B8(VDDQ) U2.B10(VDDQ) U2.D1(VDDQ) U2.D5(VDDQ) U2.D8(VDDQ) U2.D12(VDDQ) U2.F3(VDDQ) U2.F5(VDD2) U2.F8(VDD2) U2.F10(VDDQ) U2.G2(ODT_CA_A) U2.H1(VDD2) U2.H5(VDD2) U2.H8(VDD2) U2.H12(VDD2) U2.K1(VDD2) U2.K3(VDD2) U2.K10(VDD2) U2.K12(VDD2) U2.N1(VDD2) U2.N3(VDD2) U2.N10(VDD2) U2.N12(VDD2) U2.R1(VDD2) U2.R5(VDD2) U2.R8(VDD2) U2.R12(VDD2) U2.T2(ODT_CA_B) U2.U3(VDDQ) U2.U5(VDD2) U2.U8(VDD2) U2.U10(VDDQ) U2.W1(VDDQ) U2.W5(VDDQ) U2.W8(VDDQ) U2.W12(VDDQ)
DDR_CA0_A: U1.V24(DDR_A2) U2.H2(CA0_A)
DDR_CA0_B: U1.M24(DDR_A14) U2.R2(CA0_B)
DDR_CA1_A: U1.P22(DDR_A3) U2.J2(CA1_A)
DDR_CA1_B: U1.N23(DDR_A15) U2.P2(CA1_B)
DDR_CA2_A: U1.V22(DDR_A8) U2.H9(CA2_A)
DDR_CA2_B: U1.J21(DDR_A20) U2.R9(CA2_B)
DDR_CA3_A: U1.T22(DDR_A9) U2.H10(CA3_A)
DDR_CA3_B: U1.H22(DDR_A21) U2.R10(CA3_B)
DDR_CA4_A: U1.R23(DDR_A10) U2.H11(CA4_A)
DDR_CA4_B: U1.F22(DDR_A22) U2.R11(CA4_B)
DDR_CA5_A: U1.P24(DDR_A11) U2.J11(CA5_A)
DDR_CA5_B: U1.E23(DDR_A23) U2.P11(CA5_B)
DDR_CKE0_A: U1.U21(DDR_A0) U2.J4(CKE0_A)
DDR_CKE0_B: U1.L23(DDR_A12) U2.P4(CKE0_B)
DDR_CLK_A_N: U1.T24(DDR_A5) U2.J9(CK_c_A)
DDR_CLK_A_P: U1.U23(DDR_A4) U2.J8(CK_t_A)
DDR_CLK_B_N: U1.H24(DDR_A17) U2.P9(CK_c_B)
DDR_CLK_B_P: U1.J23(DDR_A16) U2.P8(CK_t_B)
DDR_CS0_A: U1.Y24(DDR_A6) U2.H4(CS0_A)
DDR_CS0_B: U1.G23(DDR_A18) U2.R4(CS0_B)
DDR_DQ0_A: U1.AB26(DDR_DQ0) U2.B2(DQ0_A)
DDR_DQ0_B: U1.F25(DDR_DQ16) U2.AA2(DQ0_B)
DDR_DQ1_A: U1.AC26(DDR_DQ1) U2.C2(DQ1_A)
DDR_DQ1_B: U1.E26(DDR_DQ17) U2.Y2(DQ1_B)
DDR_DQ2_A: U1.AB27(DDR_DQ2) U2.E2(DQ2_A)
DDR_DQ2_B: U1.F24(DDR_DQ18) U2.V2(DQ2_B)
DDR_DQ3_A: U1.AC27(DDR_DQ3) U2.F2(DQ3_A)
DDR_DQ3_B: U1.E25(DDR_DQ19) U2.U2(DQ3_B)
DDR_DQ4_A: U1.W25(DDR_DQ4) U2.F4(DQ4_A)
DDR_DQ4_B: U1.J25(DDR_DQ20) U2.U4(DQ4_B)
DDR_DQ5_A: U1.W27(DDR_DQ5) U2.E4(DQ5_A)
DDR_DQ5_B: U1.H25(DDR_DQ21) U2.V4(DQ5_B)
DDR_DQ6_A: U1.W26(DDR_DQ6) U2.C4(DQ6_A)
DDR_DQ6_B: U1.G26(DDR_DQ22) U2.Y4(DQ6_B)
DDR_DQ7_A: U1.Y25(DDR_DQ7) U2.B4(DQ7_A)
DDR_DQ7_B: U1.G25(DDR_DQ23) U2.AA4(DQ7_B)
DDR_DQ8_A: U1.R27(DDR_DQ8) U2.B11(DQ8_A)
DDR_DQ8_B: U1.J26(DDR_DQ24) U2.AA11(DQ8_B)
DDR_DQ9_A: U1.R26(DDR_DQ9) U2.C11(DQ9_A)
DDR_DQ9_B: U1.K25(DDR_DQ25) U2.Y11(DQ9_B)
DDR_DQ10_A: U1.P27(DDR_DQ10) U2.E11(DQ10_A)
DDR_DQ10_B: U1.K26(DDR_DQ26) U2.V11(DQ10_B)
DDR_DQ11_A: U1.P26(DDR_DQ11) U2.F11(DQ11_A)
DDR_DQ11_B: U1.K27(DDR_DQ27) U2.U11(DQ11_B)
DDR_DQ12_A: U1.V26(DDR_DQ12) U2.F9(DQ12_A)
DDR_DQ12_B: U1.L25(DDR_DQ28) U2.U9(DQ12_B)
DDR_DQ13_A: U1.V27(DDR_DQ13) U2.E9(DQ13_A)
DDR_DQ13_B: U1.N25(DDR_DQ29) U2.V9(DQ13_B)
DDR_DQ14_A: U1.V25(DDR_DQ14) U2.C9(DQ14_A)
DDR_DQ14_B: U1.N26(DDR_DQ30) U2.Y9(DQ14_B)
DDR_DQ15_A: U1.U25(DDR_DQ15) U2.B9(DQ15_A)
DDR_DQ15_B: U1.P25(DDR_DQ31) U2.AA9(DQ15_B)
DDR_DQMI0_A: U1.AB25(DDR_DQM0) U2.C3(DMI0_A)
DDR_DQMI0_B: U1.G27(DDR_DQM2) U2.Y3(DMI0_B)
DDR_DQMI1_A: U1.U26(DDR_DQM1) U2.C10(DMI1_A)
DDR_DQMI1_B: U1.M25(DDR_DQM3) U2.Y10(DMI1_B)
DDR_DQS0_A_N: U1.AA26(DDR_DQS0N) U2.E3(DQS0_c_A)
DDR_DQS0_A_P: U1.AA25(DDR_DQS0P) U2.D3(DQS0_t_A)
DDR_DQS0_B_N: U1.F26(DDR_DQS2N) U2.V3(DQS0_c_B)
DDR_DQS0_B_P: U1.F27(DDR_DQS2P) U2.W3(DQS0_t_B)
DDR_DQS1_A_N: U1.R25(DDR_DQS1N) U2.E10(DQS1_c_A)
DDR_DQS1_A_P: U1.T25(DDR_DQS1P) U2.D10(DQS1_t_A)
DDR_DQS1_B_N: U1.L27(DDR_DQS3N) U2.V10(DQS1_c_B)
DDR_DQS1_B_P: U1.L26(DDR_DQS3P) U2.W10(DQS1_t_B)
DDR_RESETN: R42.2 U1.E21(DDR_RESETN) U2.T11(RESET_n)
NetR1_2: R1.2 U1.K22(DDR_ZQ)
NetR2_1: R2.1 U2.A5(ZQ0)

Not connected (* = marked no-connect by the designer): U1 AA21(DDR_A30)* AA23(DDR_A27)* AB24(DDR_A26)* AC23(DDR_A28)* AC25(DDR_A7)* AD25(DDR_A1)* G21(DDR_VREF)* K24(DDR_A13)* L21(DDR_A19)* W21(DDR_A25)* W23(DDR_A31)* Y22(DDR_A29)*; U2 A1(DNU)* A2(DNU)* A8(NC)* A11(DNU)* A12(DNU)* AA1(DNU)* AA12(DNU)* AB1(DNU)* AB2(DNU)* AB11(DNU)* AB12(DNU)* B1(DNU)* B12(DNU)* G11(NC)* H3(NC)* J5(NC)* K5(NC)* K8(NC)* N5(NC)* N8(NC)* P5(NC)* R3(NC)*

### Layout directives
differential pair: DDR_CLK_A_N, DDR_CLK_A_P, DDR_CLK_B_N, DDR_CLK_B_P, DDR_DQS0_A_N, DDR_DQS0_A_P, DDR_DQS0_B_N, DDR_DQS0_B_P, DDR_DQS1_A_N, DDR_DQS1_A_P, DDR_DQS1_B_N, DDR_DQS1_B_P

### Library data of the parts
C2 C3 C10 C11 = MCD-01341: Capacitor, MLCC, 10uF, 6V3, X5R, 20%, 0603, T=0,8mm; Manufacturer_Part_Number: GRM188R60J106ME47D; Manufacturer: MURATA; Alternate_Manufacturer_Part_Number: GRM188R60J106ME84D; Part_Preference: Recommended; ECCN_US: EAR99; ECCN_EU: NEC; Provided_By: SUBCO; Component_Country_Of_Origin: Japan; ID: 3441; ShowFields: YES
C4-C8 C12-C21 = MCD-00006: Capacitor, MLCC, 100nF, 16V, X7R, +/-10%, 0402, T=0.5mm; Part_Preference: Recommended; Manufacturer: YAGEO; Manufacturer_Part_Number: CC0402KRX7R7BB104; Partial_Alternate_Internal_Part_Number: MCD-03299; Order_Code_RS: 616-9701; Component_Country_Of_Origin: China; Alternate_EMS: M; ShowFields: YES; ID: 2474
R1 R2 = MCD-02253: Resistor, 240R, 0201, +/-1%, 1/20W; Part_Preference: Recommended; Manufacturer: YAGEO; Manufacturer_Part_Number: RC0201FR-07240RL; Component_Country_Of_Origin: China; ID: 4353; ShowFields: YES
R42 = MCD-00053: as R220 on sheet USB3
U1 = MCD-03375: as U1 on sheet USB3
U2 = MCD-04160: Memory, LPDDR4 SDRAM,1V8, 32Gbit, 2133MHz; Part_Type: IC; Part_Preference: Recommended; Manufacturer: MICRON; ShowFields: YES; ID: 6276

## Sheet SDcard_eMMC.SchDoc: SDcard_eMMC
size A3; Date: Not used; ApprovedBy: Not used; CheckedBy: Not used; Author: Not used; CompanyName: STMicroelectronics; DrawnBy: Not used; Engineer: Not used; Organization: Not used; Address1: Not used; Address2: Not used; Address3: Not used; Address4: Not used; DocumentNumber: Not used; Revision: Not used; SheetNumber: 7; SheetTotal: 18
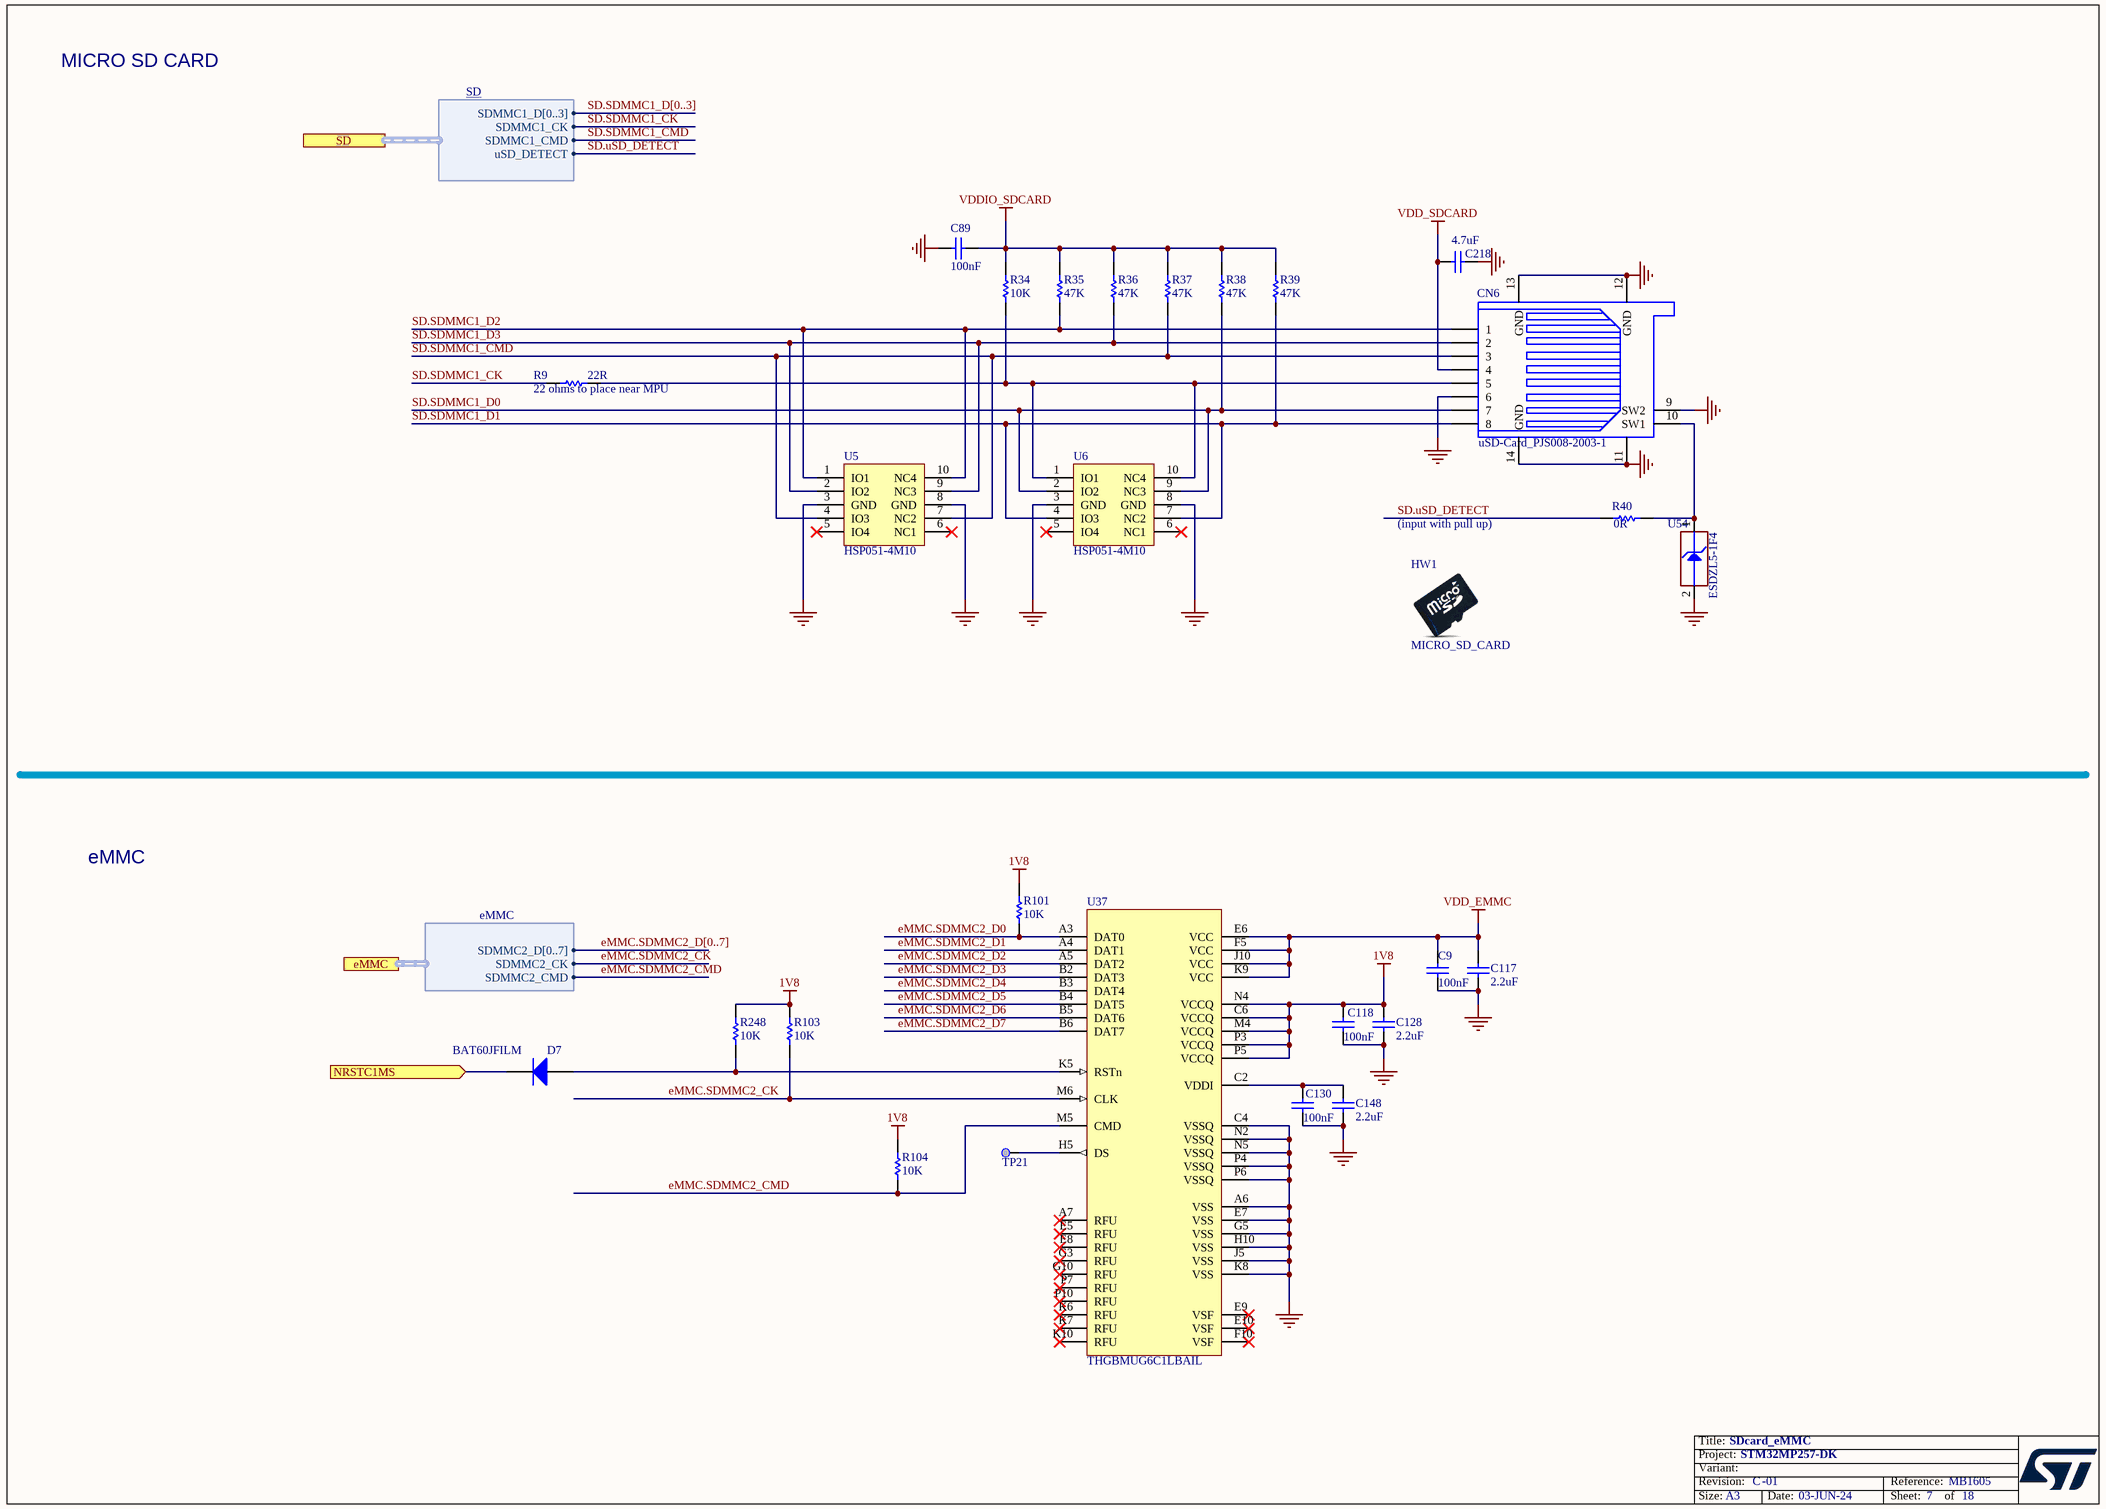
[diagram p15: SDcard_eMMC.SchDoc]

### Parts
C9  value 100nF  [C0402]  (hidden comment: Capacitor)
C89  value 100nF  [C0402]  (hidden comment: Capacitor)
C117  value 2.2uF  [C0402]  (hidden comment: Capacitor)
C118  value 100nF  [C0402]  (hidden comment: Capacitor)
C128  value 2.2uF  [C0402]  (hidden comment: Capacitor)
C130  value 100nF  [C0402]  (hidden comment: Capacitor)
C148  value 2.2uF  [C0402]  (hidden comment: Capacitor)
C218  value 4.7uF  [C0402]  (hidden comment: Capacitor)
CN6  value uSD-Card_PJS008-2003-1  [CON_MICROSD_YAMAICHI_PJS008-2003-1]  (hidden comment: microSD-PJS008-2003)
D7  BAT60JFILM  [DIO_SOD323]
HW1  Micro_SD_card  (mechanical)
R9  value 22R  [R0201_H0P23]  (hidden comment: Resistor)
R34  value 10K  [R0402]  (hidden comment: Resistor)
R35  value 47K  [R0402]  (hidden comment: Resistor)
R36  value 47K  [R0402]  (hidden comment: Resistor)
R37  value 47K  [R0402]  (hidden comment: Resistor)
R38  value 47K  [R0402]  (hidden comment: Resistor)
R39  value 47K  [R0402]  (hidden comment: Resistor)
R40  value 0R  [R0402]  (hidden comment: Resistor)
R101  value 10K  [R0402]  (hidden comment: Resistor)
R103  value 10K  [R0402]  (hidden comment: Resistor)
R104  value 10K  [R0402]  (hidden comment: Resistor)
R248  value 10K  [R0402]  (hidden comment: Resistor)
TP21  Test Point  [TP_SMD_1MM]  (value not drawn)  (no BOM)
U5  HSP051-4M10  [ESD_UQFN-10L_2P5X1_P050]
U6  HSP051-4M10  [ESD_UQFN-10L_2P5X1_P050]
U37  value THGBMUG6C1LBAIL  [ICC_WFBGA153_13X11P5_P050]  (hidden comment: eMMC_THGBMUG6C1LBAIL)
U54  value ESDZL5-1F4  [ESD_ST0201]  (hidden comment: ESD-TRANSIL)

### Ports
eMMC (harness eMMC), NRSTC1MS (in), SD (harness SD)

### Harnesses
SD: SDMMC1_D[0..3], SDMMC1_CK, SDMMC1_CMD, uSD_DETECT
eMMC: SDMMC2_CK, SDMMC2_CMD, SDMMC2_D[0..7]

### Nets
1V8: C118.2 C128.2 R101.2 R103.2 R104.2 R248.2 U37.C6(VCCQ) U37.M4(VCCQ) U37.N4(VCCQ) U37.P3(VCCQ) U37.P5(VCCQ)
GND: C9.1 C89.1 C117.1 C118.1 C128.1 C130.1 C148.1 C218.1 CN6.6 CN6.9(SW2) CN6.11(GND) CN6.12(GND) CN6.13(GND) CN6.14(GND) U5.3(GND) U5.8(GND) U6.3(GND) U6.8(GND) U37.A6(VSS) U37.C4(VSSQ) U37.E7(VSS) U37.G5(VSS) U37.H10(VSS) U37.J5(VSS) U37.K8(VSS) U37.N2(VSSQ) U37.N5(VSSQ) U37.P4(VSSQ) U37.P6(VSSQ) U54.2(GND)
VDD_EMMC: C9.2 C117.2 U37.E6(VCC) U37.F5(VCC) U37.J10(VCC) U37.K9(VCC)
VDD_SDCARD: C218.2 CN6.4
VDDIO_SDCARD: C89.2 R34.2 R35.2 R36.2 R37.2 R38.2 R39.2
eMMC.SDMMC2_CK: R103.1 U37.M6(CLK) ; port eMMC.SDMMC2_CK
eMMC.SDMMC2_CMD: R104.1 U37.M5(CMD) ; port eMMC.SDMMC2_CMD
eMMC.SDMMC2_D0: R101.1 U37.A3(DAT0)
eMMC.SDMMC2_D1: U37.A4(DAT1)
eMMC.SDMMC2_D2: U37.A5(DAT2)
eMMC.SDMMC2_D3: U37.B2(DAT3)
eMMC.SDMMC2_D4: U37.B3(DAT4)
eMMC.SDMMC2_D5: U37.B4(DAT5)
eMMC.SDMMC2_D6: U37.B5(DAT6)
eMMC.SDMMC2_D7: U37.B6(DAT7)
NRSTC1MS: D7.2(K) ; port NRSTC1MS
SD.SDMMC1_CK: R9.1 ; port SD.SDMMC1_CK
SD.SDMMC1_CMD: CN6.3 R37.1 U5.4(IO3) U5.7(NC2) ; port SD.SDMMC1_CMD
SD.SDMMC1_D0: CN6.7 R38.1 U6.2(IO2) U6.9(NC3)
SD.SDMMC1_D1: CN6.8 R39.1 U6.4(IO3) U6.7(NC2)
SD.SDMMC1_D2: CN6.1 R35.1 U5.1(IO1) U5.10(NC4)
SD.SDMMC1_D3: CN6.2 R36.1 U5.2(IO2) U5.9(NC3)
SD.uSD_DETECT: R40.1 ; port SD.uSD_DETECT
NetC130_2: C130.2 C148.2 U37.C2(VDDI)
NetCN6_5: CN6.5 R9.2 R34.1 U6.1(IO1) U6.10(NC4)
NetCN6_10: CN6.10(SW1) R40.2 U54.1(IO1)
NetD7_1: D7.1(A) R248.1 U37.K5(RSTn)
NetTP21_1: TP21.1 U37.H5(DS)

Not connected (* = marked no-connect by the designer): U5 5(IO4)* 6(NC1)*; U6 5(IO4)* 6(NC1)*; U37 A7(RFU)* E5(RFU)* E8(RFU)* E9(VSF)* E10(VSF)* F10(VSF)* G3(RFU)* G10(RFU)* K6(RFU)* K7(RFU)* K10(RFU)* P7(RFU)* P10(RFU)*

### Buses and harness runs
bus eMMC.SDMMC2_D[0..7]
bus SD.SDMMC1_D[0..3]

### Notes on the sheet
- MICRO SD CARD
- (near R9) 22 ohms to place near MPU
- (near HW1) (input with pull up)
- eMMC

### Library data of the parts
C9 C89 C118 C130 = MCD-00006: Capacitor, MLCC, 100nF, 16V, X7R, +/-10%, 0402, T=0.5mm; Part_Preference: Recommended; Manufacturer: YAGEO; Manufacturer_Part_Number: CC0402KRX7R7BB104; Alternate_Manufacturer: MURATA; Alternate_Manufacturer_Part_Number: GCM155R71C104KA55D; Partial_Alternate_Internal_Part_Number: MCD-03299; Order_Code_RS: 616-9701; Component_Country_Of_Origin: China; Alternate_EMS: M; ID: 2474; ShowFields: YES
C117 C128 C148 = MCD-02606: Capacitor, MLCC, 2.2uF, 6.3V, X5R, +/-10%, 0402, T=0.5mm; Part_Preference: Recommended; Manufacturer: YAGEO; Manufacturer_Part_Number: CC0402KRX5R5BB225; Order_Code_RS: 1992205; ShowFields: YES; ID: 4712; Component_Country_Of_Origin: China°
C218 = MCD-01356: Capacitor, MLCC, 4.7uF, 6V3, X5R, 20%, 0402, T=0,5mm; Manufacturer_Part_Number: GRM155R60J475ME47; Manufacturer: MURATA; Alternate_Manufacturer_Part_Number: GRM155R60J475ME87; Part_Preference: Recommended; Provided_By: SUBCO; ECCN_EU: NEC; ECCN_US: EAR99; Order_Code_RS: 814-5230; Component_Country_Of_Origin: Japan; ID: 3456; ShowFields: YES
CN6 = MCD-00023: MicroSD Card Conn, Reversed-Type, Mnt Push-Push, Positionning holes; Manufacturer_Part_Number: PJS008-2003-1; Manufacturer: YAMAICHI; Part_Type: Connector; Part_Preference: Recommended; Provided_By: SUBCO; Component_Country_Of_Origin: Unknown; ID: 2492; ShowFields: YES
D7 = MCD-00034: BMS_Part_Number: 9151097; Part_Type: Diode; Part_Preference: Recommended; Manufacturer: STMICROELECTRONICS; Manufacturer_HQ_COO: EU; Component_Country_Of_Origin: China; ShowFields: YES; ID: 2483
HW1 = MCD-03307: MICRO_SD_CARD, SANDISK, 16GB, Class10, 3V; Part_Type: Mechanical; Part_Preference: Recommended; Manufacturer_Part_Number: SDSDQAD-016G; Order_Code_RS: 220-8618; Component_Country_Of_Origin: China°; ShowFields: YES; ID: 5423
R9 = MCD-02978: Resistor, 22R, 0201, +/-1%, 1/20W; Manufacturer_Part_Number: RC0201FR-0722RL; Manufacturer: YAGEO; Part_Preference: Recommended; Order_Code_RS: 198-7593; ID: 5094; ShowFields: YES; Component_Country_Of_Origin: China
R34 R101 R103 R104 R248 = MCD-00053: Resistor,10K,0402,1%,1/16W; Manufacturer_Part_Number: RC0402FR-0710KL; Manufacturer: YAGEO; BMS_Part_Number: 9131590; Part_Preference: Recommended; ECCN_US: EAR99; ECCN_EU: NEC; Provided_By: SUBCO; Component_Country_Of_Origin: China; ID: 2539; ShowFields: YES
R35-R39 = MCD-00063: Resistor,47K,0402,1%,1/16W; Manufacturer_Part_Number: RC0402FR-0747KL; Manufacturer: YAGEO; Part_Preference: Recommended; ECCN_US: EAR99; ECCN_EU: NEC; Provided_By: SUBCO; Component_Country_Of_Origin: China; ID: 2528; ShowFields: YES
R40 = MCD-00052: Resistor,0R,0402,5%,1/16W; Manufacturer_Part_Number: RC0402JR-070RL; Manufacturer: YAGEO; Part_Preference: Recommended; ECCN_US: EAR99; ECCN_EU: NEC; Provided_By: SUBCO; Order_Code_RS: 618-5804; Component_Country_Of_Origin: China; ID: 2540; ShowFields: YES
TP21 = MCD-00074: as TP34 on sheet USB3
U5 U6 = MCD-00667: 4-line ESD protection for high speed lines; Part_Type: Diode; Manufacturer: STMICROELECTRONICS; BMS_Part_Number: 9179041; Manufacturer_HQ_COO: EU; Part_Preference: Recommended; ECCN_US: EAR99; ECCN_EU: NEC; Provided_By: SUBCO with ST control; Component_Country_Of_Origin: Philippines; ID: 3081; ShowFields: YES
U37 = MCD-04155: Memory, eMMC, 3V3, 8Gbit, 52MHz , V5.1; Part_Type: IC; Part_Preference: Recommended; Manufacturer: KIOXIA; ShowFields: YES; ID: 6271
U54 = MCD-03501: as U11 on sheet CAMERA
